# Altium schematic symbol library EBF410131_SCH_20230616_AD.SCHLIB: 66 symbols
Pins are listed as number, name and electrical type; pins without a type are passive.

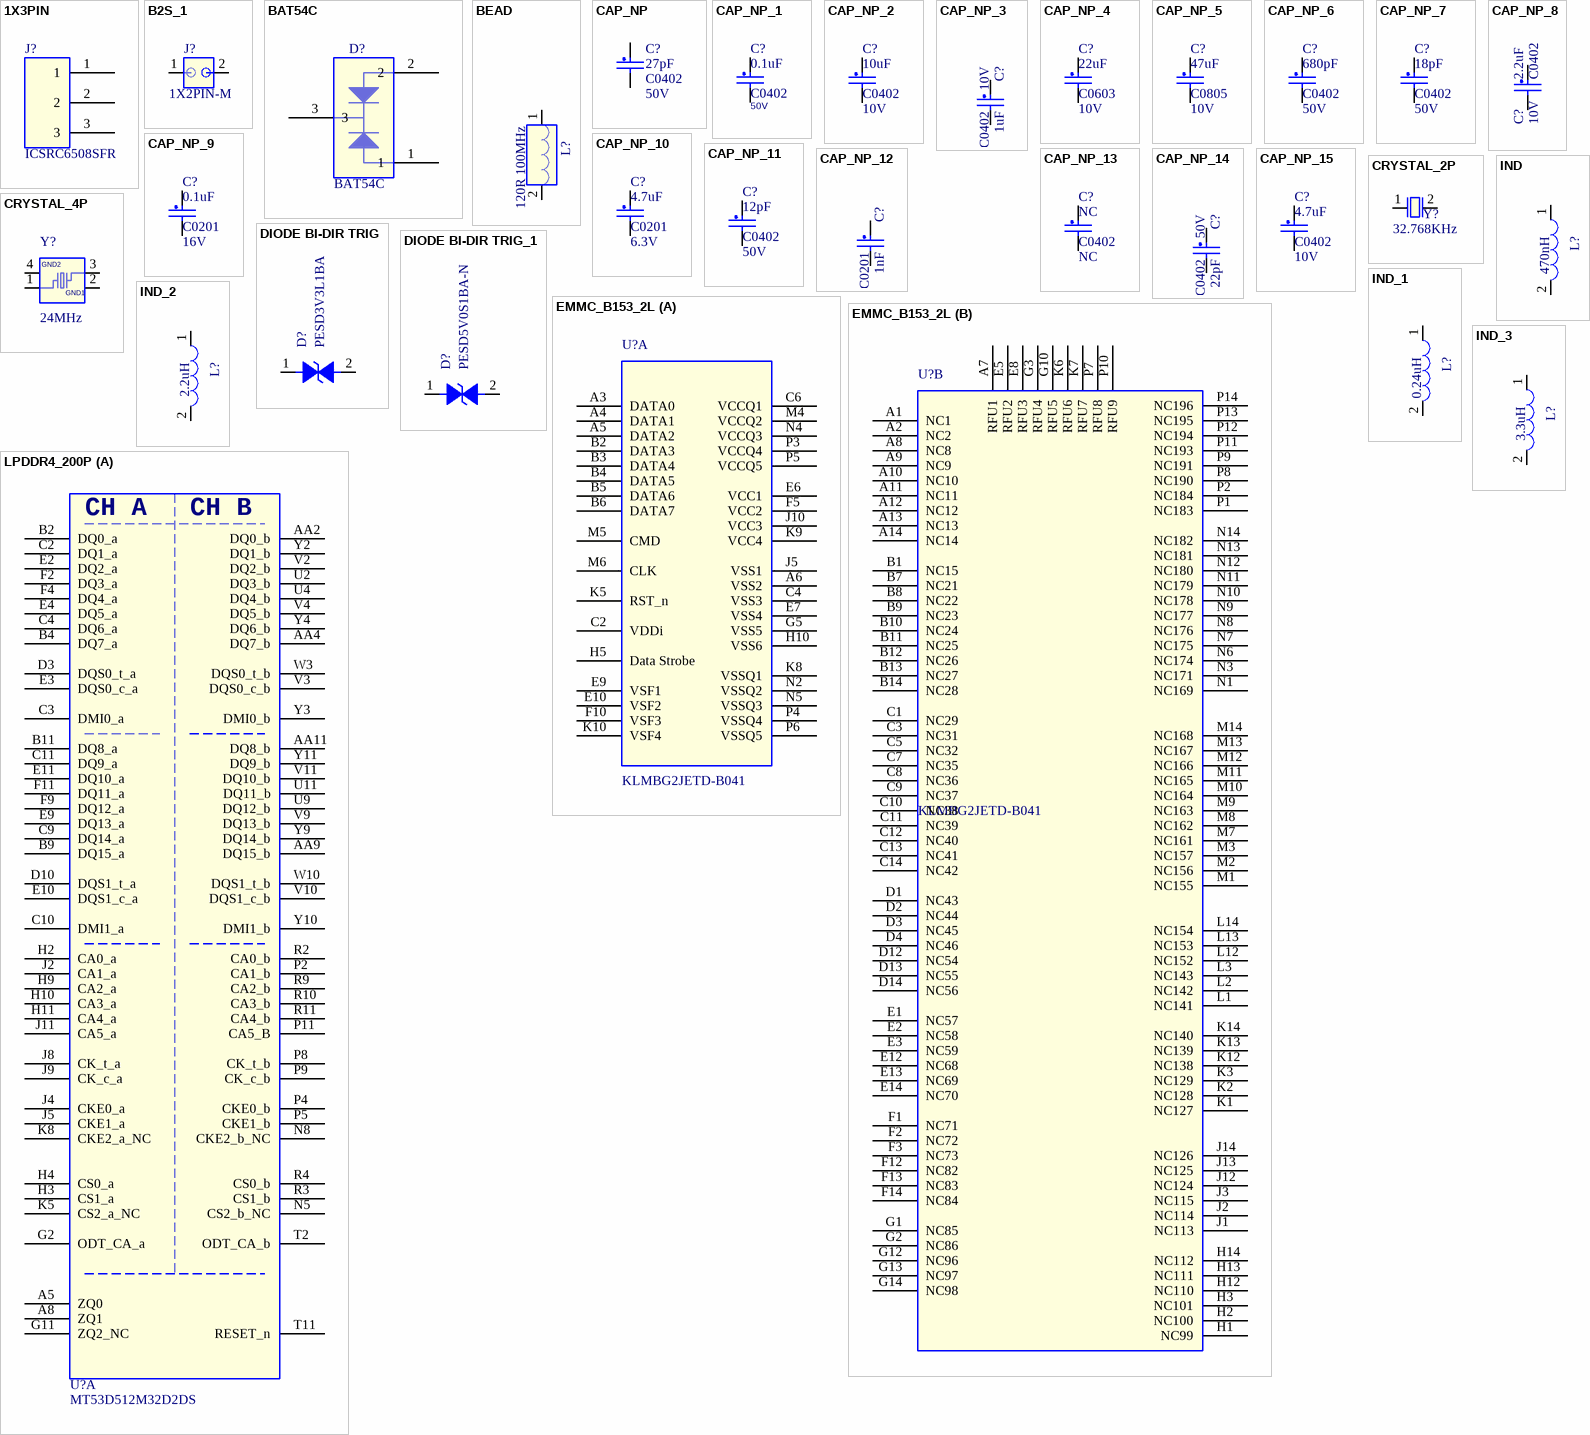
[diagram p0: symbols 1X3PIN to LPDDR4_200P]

## 1X3PIN
designator J?, comment ICSRC6508SFR
生命周期: 量产; 价格: 0.1; 规格书: ICT_ICSRC6508SFR.pdf; 类别: 屏蔽夹; 品牌: ICT; 条码: EBFCIS230316171123; 规格: ICSRC6508SFR 6.5x0.8x1.2(mm)
footprint ICSRC6508SFR
pins: 1, 2, 3

## B2S_1
designator J?, comment 1X2PIN-M
PCB Footprint: HDR-1RX2-1R50-TM-VR; 规格书: 州日_单排针_直插_2P54.pdf; 规格: 排针 总PIN数2 间距2.54mm 黑色直插; 条码: EBF29020033; 类别: 直插单排排针; 生命周期: 量产
footprint HDR-1RX2-1R50-TM-VR
pins: 1, 2

## BAT54C
designator D?
PCB Footprint: SOT23; 规格: 肖特基二极管 直流反向耐压30V 平均整流电流200mA 正向压降1V@100mA SOT-23; 条码: EBF29140014; 品牌: 萨科微; 类别: 贴片肖特基二极管; 规格书: BAT54C.pdf; 价格: 0.068489; 生命周期: 量产; 丝印: KL3
footprint SOT23
pins: 1, 2, 3

## BEAD
designator L?, comment 120R 100MHz
CLASS: DISCRETE; 规格: 磁珠120Ω @100MHz 额定电流1A 直流电阻120mΩ; 规格编号: PZ1005U121-1R0TF; 条码: EBF29050044; 品牌: 顺络; 类别: 贴片磁珠0402; 规格书: 顺络-磁珠120Ω±25%100MHZ.pdf; 价格: 0.020259; 生命周期: 量产; PCB Footprint: L0402
footprint L0402
pins: 1, 2

## CAP_NP
designator C?, comment 27pF  PCB Footprint: C0402  Voltage: 50V
CLASS: DISCRETE; 规格: 贴片电容27pF 5% 50V C0G 0402; 规格编号: 0402CG270J500NT; 条码: EBF29060296; 品牌: 风华; 类别: 贴片电容0402; 规格书: 风华电容.pdf; 价格: 0.003278; 生命周期: 量产
footprint C0402
pins: 1, 2

## CAP_NP_1
designator C?, comment 0.1uF  PCB Footprint: C0402  Voltage: 50V
CLASS: DISCRETE; 生命周期: 量产; 价格: 0.029826; 规格书: 风华电容.pdf; 类别: 贴片电容0402; 品牌: 风华; 条码: EBF29060118; 规格编号: 0402X104K500NT; 规格: 贴片电容0.1uF 10% 50V X5R 0402
footprint C0402
pins: 1, 2

## CAP_NP_2
designator C?, comment 10uF  PCB Footprint: C0402  Voltage: 10V
CLASS: DISCRETE; 生命周期: 量产; 价格: 0.518415; 规格书: 三星电容.pdf; 类别: 贴片电容0402; 品牌: 三星; 条码: EBF29060247; 规格编号: CL05A106MP8NUB8; 规格: 贴片电容10uF 20% 10V X5R 0402
footprint C0402
pins: 1, 2

## CAP_NP_3
designator C?, comment 1uF  PCB Footprint: C0402  Voltage: 10V
CLASS: DISCRETE; 规格: 贴片电容1uF 10% 10V X5R 0402; 规格编号: 0402X105K100NT; 条码: EBF29060121; 品牌: 风华; 类别: 贴片电容0402; 规格书: 风华电容.pdf; 价格: 0.01191; 生命周期: 量产
footprint C0402
pins: 1, 2

## CAP_NP_4
designator C?, comment 22uF  PCB Footprint: C0603  Voltage: 10V
CLASS: DISCRETE; 规格: 贴片电容22uF 20% 10V X5R 0603; 规格编号: CL10A226MP8NUNE; 条码: EBF29060163; 品牌: 三星; 类别: 贴片电容0603; 规格书: 三星电容.pdf; 价格: 0.078818; 生命周期: 量产
footprint C0603
pins: 1, 2

## CAP_NP_5
designator C?, comment 47uF  PCB Footprint: C0805  Voltage: 10V
CLASS: DISCRETE; 生命周期: 量产; 价格: 0.368494; 规格书: 风华电容.pdf; 类别: 贴片电容0805; 品牌: 风华; 条码: EBF29060212; 规格编号: 0805X476M100NT; 规格: 贴片电容47uF 20% 10V X5R 0805
footprint C0805
pins: 1, 2

## CAP_NP_6
designator C?, comment 680pF  PCB Footprint: C0402  Voltage: 50V
CLASS: DISCRETE; 规格: 贴片电容680pF 10% 50V X7R 0402; 规格编号: 0402B681K500NT; 条码: EBF29060295; 品牌: 风华; 类别: 贴片电容0402; 规格书: 风华电容.pdf; 价格: 0.003453; 生命周期: 量产
footprint C0402
pins: 1, 2

## CAP_NP_7
designator C?, comment 18pF  PCB Footprint: C0402  Voltage: 50V
CLASS: DISCRETE; 生命周期: 量产; 价格: 0.00515; 规格书: 风华电容.pdf; 类别: 贴片电容0402; 品牌: 风华; 条码: EBF29060235; 规格编号: 0402CG180J500NT; 规格: 贴片电容18pF 5% 50V C0G 0402
footprint C0402
pins: 1, 2

## CAP_NP_8
designator C?, comment 2.2uF  PCB Footprint: C0402  Voltage: 10V
CLASS: DISCRETE; 生命周期: 量产; 价格: 0.015858; 规格书: 三星电容.pdf; 类别: 贴片电容0402; 品牌: 三星; 条码: EBF29060265; 规格编号: CL05A225KP5NSNC; 规格: 贴片电容2.2uF 10% 10V X5R 0402
footprint C0402
pins: 1, 2

## CAP_NP_9
designator C?, comment 0.1uF  PCB Footprint: C0201  Voltage: 16V
CLASS: DISCRETE; 生命周期: 量产; 规格书: 三星电容.pdf; 类别: 贴片电容0201; 品牌: 三星; 条码: EBF29060189; 规格编号: CL03A104KO3NNNC; 规格: 贴片电容0.1uF 10% 16V X5R 0201; 价格: 0.006
footprint C0201
pins: 1, 2

## CAP_NP_10
designator C?, comment 4.7uF  PCB Footprint: C0201  Voltage: 6.3V
CLASS: DISCRETE; 生命周期: 量产; 价格: 0.399715; 规格书: 村田贴片电容.pdf; 类别: 贴片电容0201; 品牌: 村田; 条码: EBF29060234; 规格编号: GRM035R60J475ME15D; 规格: 贴片电容4.7uF 20% 6.3V X5R 0201
footprint C0201
pins: 1, 2

## CAP_NP_11
designator C?, comment 12pF  PCB Footprint: C0402  Voltage: 50V
CLASS: DISCRETE; 规格: 贴片电容12pF 5% 50V C0G 0402; 规格编号: 0402CG120J500NT; 条码: EBF29060297; 品牌: 风华; 类别: 贴片电容0402; 规格书: 风华电容.pdf; 价格: 0.003248; 生命周期: 量产
footprint C0402
pins: 1, 2

## CAP_NP_12
designator C?, comment 1nF  PCB Footprint: C0201
CLASS: DISCRETE; 生命周期: 量产; 价格: 0.00414; 规格书: 微容0201系列贴片电容.pdf; 类别: 贴片电容0201; 品牌: 微容; 条码: EBF29060303; 规格编号: V102K0201X7R500NAT; 规格: 贴片电容1nF 10% 50V X7R 0201
footprint C0201
pins: 1, 2

## CAP_NP_13
designator C?, comment NC  PCB Footprint: C0402
CLASS: DISCRETE; 类别: 贴片电容0402; 条码: EBF29060149; 规格: 贴片电容NC 预留
footprint C0402
pins: 1, 2

## CAP_NP_14
designator C?, comment 22pF  PCB Footprint: C0402  Voltage: 50V
CLASS: DISCRETE; 规格: 贴片电容22pF 5% 50V C0G 0402; 规格编号: 0402CG220J500NT; 条码: EBF29060220; 品牌: 三星; 类别: 贴片电容0402; 规格书: 三星电容.pdf; 价格: 0.004645; 生命周期: 量产
footprint C0402
pins: 1, 2

## CAP_NP_15
designator C?, comment 4.7uF  PCB Footprint: C0402  Voltage: 10V
CLASS: DISCRETE; 规格: 贴片电容4.7uF 10% 10V X5R 0402; 规格编号: CC0402KRX5R6BB475; 条码: EBF29060248; 品牌: 国巨; 类别: 贴片电容0402; 规格书: 国巨-贴片电容.pdf; 价格: 0.059058; 生命周期: 量产
footprint C0402
pins: 1, 2

## CRYSTAL_2P
designator Y?, comment 32.768KHz
规格: 无源晶振32.768KHz 70KΩ 9pF 3215; 规格编号: Q13FC1350000300; 条码: EBF29100004; 品牌: 爱普生; 类别: 贴片晶振 3215; 规格书: 爱普生-32.768KHz.pdf; 价格: 2.57; 生命周期: 量产; PCB Footprint: 3215
footprint 3215
pins: 1, 2

## CRYSTAL_4P
designator Y?, comment 24MHz
CLASS: IC; 规格: 无源晶振24MHZ 40Ω 12pF 3225; 规格编号: SX32Y024000BC1T; 条码: EBF29100003; 品牌: 泰晶; 类别: 贴片晶振 3225; PCB Footprint: 3225; 规格书: 泰晶-24MHz无源晶振.pdf; 价格: 0.436916; 生命周期: 量产
footprint 3225
pins: 1, 2 GND1 (power), 3, 4 GND2 (power)

## DIODE BI-DIR TRIG
designator D?, comment PESD3V3L1BA
PCB Footprint: sod323_t; 丝印: AB; 生命周期: 量产; 价格: 0.31497; 规格书: 安世-PESD3V3L1BA-115.pdf; 类别: 贴片ESD; 品牌: 安世; 条码: EBF29140003; 规格编号: PESD3V3L1BA 115; 规格: 防静电保护ESD二极管 箝位电压26V 击穿电压5.8V 反向关断电压3.3V
footprint D0603/SMD
footprint sod323_t
pins: 1, 2

## DIODE BI-DIR TRIG_1
designator D?, comment PESD5V0S1BA-N
PCB Footprint: SOD323; 规格: 防静电保护ESD二极管 箝位电压21V 击穿电压6V 反向关断电压5V; 条码: EBF29140021; 品牌: 伯恩半导体; 类别: 贴片ESD; 规格书: 伯恩半导体-PESD5V0S1BA-N.pdf; 价格: 0.196644; 生命周期: 量产
footprint D0603/SMD
footprint SOD323
pins: 1, 2

## EMMC_B153_2L
designator U?, comment KLMBG2JETD-B041
规格: eMMC 容量：32G 工作电压 Interface power : VDD (1.70V ~ 1.95V or 2.7V ~ 3.6V) Memory power : VDDF (2.7V ~ 3.6V); 条码: EBF2950033; 品牌: 三星; 类别: 存储器-eMMC; 规格书: KLMBG2JETD-B041.pdf; 生命周期: 量产
footprint FBGA153_0P5_11P5X13
part A pins: A3 DATA0, A4 DATA1, A5 DATA2, A6 VSS2, B2 DATA3, B3 DATA4, B4 DATA5, B5 DATA6, B6 DATA7, C2 VDDi, C4 VSS3, C6 VCCQ1, E6 VCC1, E7 VSS4, E9 VSF1, E10 VSF2, F5 VCC2, F10 VSF3, G5 VSS5, H5 Data Strobe, H10 VSS6, J5 VSS1, J10 VCC3, K5 RST_n, K8 VSSQ1, K9 VCC4, K10 VSF4, M4 VCCQ2, M5 CMD, M6 CLK, N2 VSSQ2, N4 VCCQ3, N5 VSSQ3, P3 VCCQ4, P4 VSSQ4, P5 VCCQ5, P6 VSSQ5
part B pins: A1 NC1, A2 NC2, A7 RFU1, A8 NC8, A9 NC9, A10 NC10, A11 NC11, A12 NC12, A13 NC13, A14 NC14, B1 NC15, B7 NC21, B8 NC22, B9 NC23, B10 NC24, B11 NC25, B12 NC26, B13 NC27, B14 NC28, C1 NC29, C3 NC31, C5 NC32, C7 NC35, C8 NC36, C9 NC37, C10 NC38, C11 NC39, C12 NC40, C13 NC41, C14 NC42, D1 NC43, D2 NC44, D3 NC45, D4 NC46, D12 NC54, D13 NC55, D14 NC56, E1 NC57, E2 NC58, E3 NC59, E5 RFU2, E8 RFU3, E12 NC68, E13 NC69, E14 NC70, F1 NC71, F2 NC72, F3 NC73, F12 NC82, F13 NC83, F14 NC84, G1 NC85, G2 NC86, G3 RFU4, G10 RFU5, G12 NC96, G13 NC97, G14 NC98, H1 NC99, H2 NC100, H3 NC101, H12 NC110, H13 NC111, H14 NC112, J1 NC113, J2 NC114, J3 NC115, J12 NC124, J13 NC125, J14 NC126, K1 NC127, K2 NC128, K3 NC129, K6 RFU6, K7 RFU7, K12 NC138, K13 NC139, K14 NC140, L1 NC141, L2 NC142, L3 NC143, L12 NC152, L13 NC153, L14 NC154, M1 NC155, M2 NC156, M3 NC157, M7 NC161, M8 NC162, M9 NC163, M10 NC164, M11 NC165, M12 NC166, M13 NC167, M14 NC168, N1 NC169, N3 NC171, N6 NC174, N7 NC175, N8 NC176, N9 NC177, N10 NC178, N11 NC179, N12 NC180, N13 NC181, N14 NC182, P1 NC183, P2 NC184, P7 RFU8, P8 NC190, P9 NC191, P10 RFU9, P11 NC193, P12 NC194, P13 NC195, P14 NC196

## IND
designator L?, comment 470nH
CLASS: DISCRETE; 生命周期: 量产; 价格: 0.175312; 规格书: 佳邦_WIP252012P-R47ML.pdf; 类别: 贴片电感2520; 品牌: 佳邦; 条码: EBF29050046; 规格编号: WIP252012P-R47ML; 规格: 功率电感470nH ±20% 4.18A 直流电阻22mΩ; PCB Footprint: L2520
footprint L2520
pins: 1, 2

## IND_1
designator L?, comment 0.24uH
CLASS: DISCRETE; 规格: 功率电感0.24uH ±20% 4.05A 直流电阻19mΩ; 规格编号: WPN252012HR24MT; 条码: EBF29050066; 品牌: 顺络; 类别: 贴片电感2520; 规格书: 顺络WPN系列功率电感.pdf; 生命周期: 量产; PCB Footprint: L2520
footprint L2520
pins: 1, 2

## IND_2
designator L?, comment 2.2uH
CLASS: DISCRETE; 规格: 功率电感2.2uH 2.2uH ±20% 2.06A 85mΩ; 规格编号: WIP252012P-2R2ML; 条码: EBFCIS220927171910; 品牌: 佳邦; 类别: 贴片电感2520; 规格书: 佳邦_ WIP252012P-2R2ML.pdf; 价格: 0.129914; 生命周期: 量产; PCB Footprint: L2520
footprint L2520
pins: 1, 2

## IND_3
designator L?, comment 3.3uH
CLASS: DISCRETE; 生命周期: 量产; 规格书: 台庆-功率电感.pdf; 类别: 贴片电感0402; 品牌: 台庆; 条码: EBF29050040; 规格: 贴片电感3.3uH ±20% 3A 直流电阻69mΩ; 规格编号: TMPC0402HP-3R3MG-Z02; 价格: 1.5992; PCB Footprint: l4520
footprint l4520
pins: 1, 2

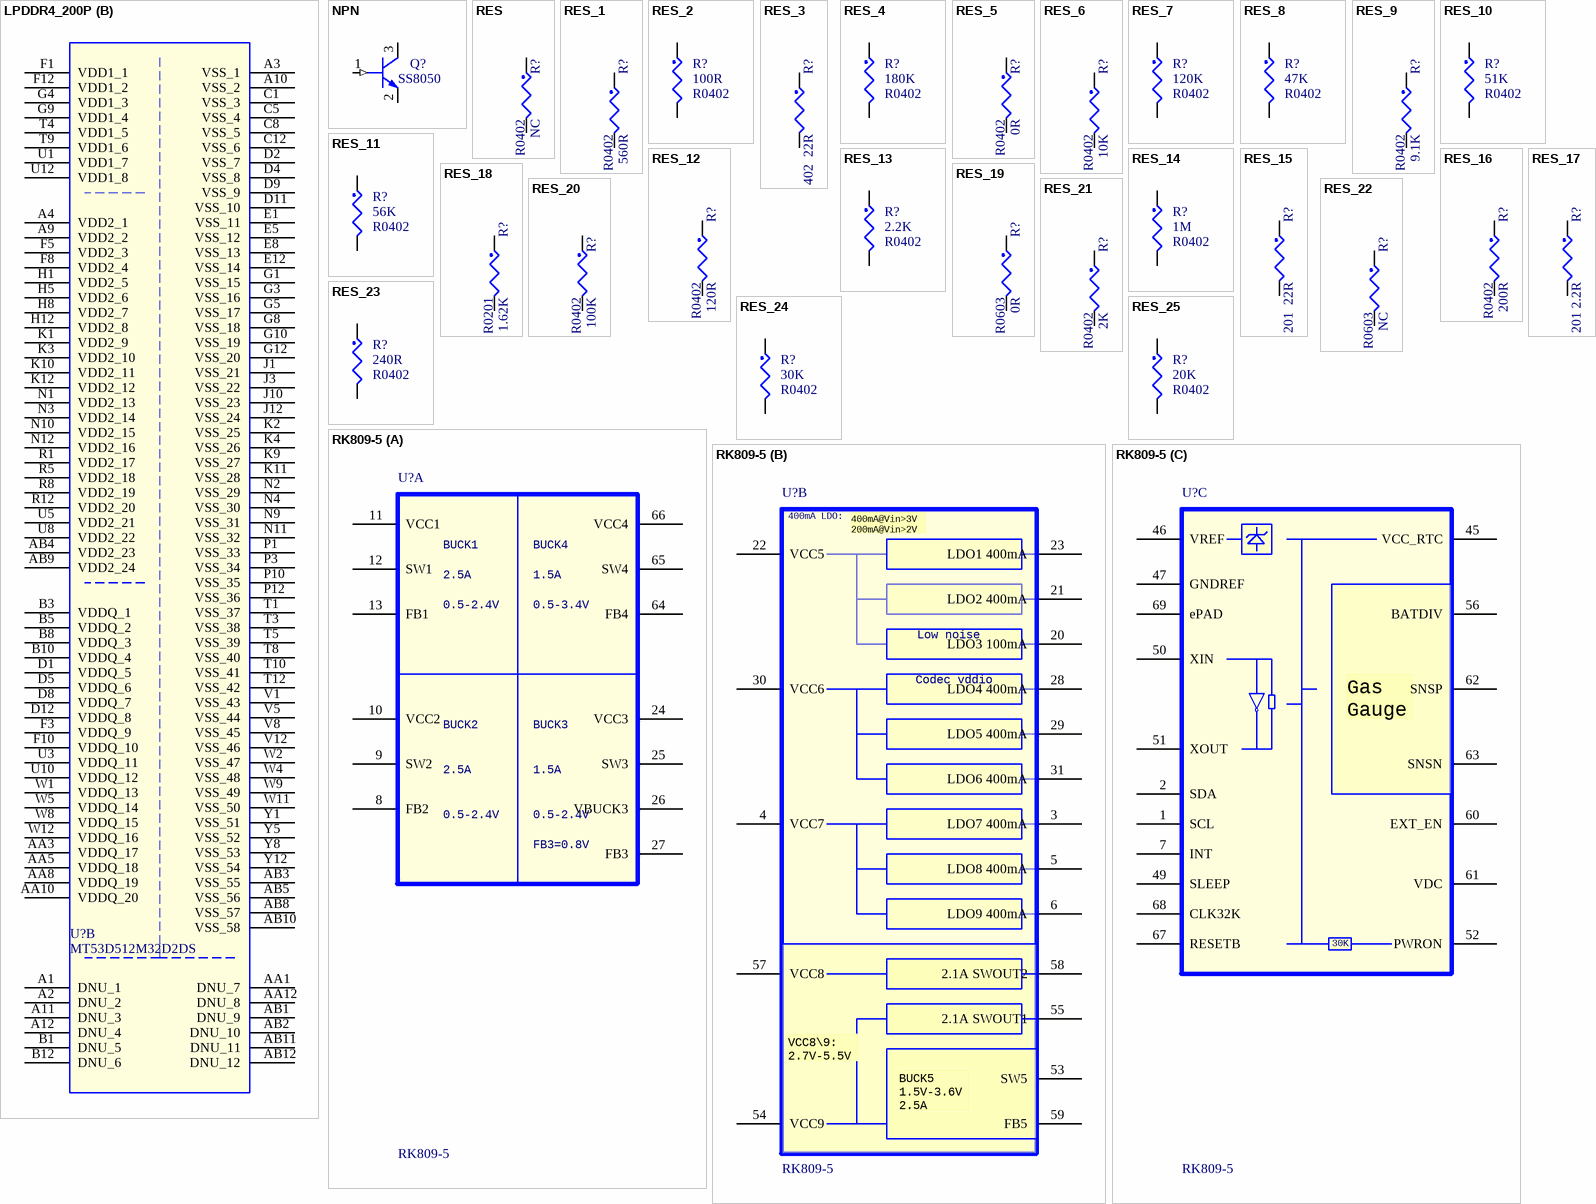
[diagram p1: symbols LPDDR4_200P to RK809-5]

## LPDDR4_200P
designator U?, comment MT53D512M32D2DS
PCB Footprint: bga200_15r00x10r00x0r90; 规格: DDR4 SDRAM 大小：16Gb(512Mx32); 规格编号: MT53D512M32D2DS-053WT:D; 条码: EBF2950034; 品牌: 镁光; 类别: 存储器-DRAM; 规格书: Micron-Tech-MT53D512M32D2DS-053-WT-D.pdf; 生命周期: 量产
footprint bga200_15r00x10r00x0r90
part A pins: A5 ZQ0, A8 ZQ1, AA2 DQ0_b, AA4 DQ7_b, AA9 DQ15_b, AA11 DQ8_b, B2 DQ0_a, B4 DQ7_a, B9 DQ15_a, B11 DQ8_a, C2 DQ1_a, C3 DMI0_a, C4 DQ6_a, C9 DQ14_a, C10 DMI1_a, C11 DQ9_a, D3 DQS0_t_a, D10 DQS1_t_a, E2 DQ2_a, E3 DQS0_c_a, E4 DQ5_a, E9 DQ13_a, E10 DQS1_c_a, E11 DQ10_a, F2 DQ3_a, F4 DQ4_a, F9 DQ12_a, F11 DQ11_a, G2 ODT_CA_a, G11 ZQ2_NC, H2 CA0_a, H3 CS1_a, H4 CS0_a, H9 CA2_a, H10 CA3_a, H11 CA4_a, J2 CA1_a, J4 CKE0_a, J5 CKE1_a, J8 CK_t_a, J9 CK_c_a, J11 CA5_a, K5 CS2_a_NC, K8 CKE2_a_NC, N5 CS2_b_NC, N8 CKE2_b_NC, P2 CA1_b, P4 CKE0_b, P5 CKE1_b, P8 CK_t_b, P9 CK_c_b, P11 CA5_B, R2 CA0_b, R3 CS1_b, R4 CS0_b, R9 CA2_b, R10 CA3_b, R11 CA4_b, T2 ODT_CA_b, T11 RESET_n, U2 DQ3_b, U4 DQ4_b, U9 DQ12_b, U11 DQ11_b, V2 DQ2_b, V3 DQS0_c_b, V4 DQ5_b, V9 DQ13_b, V10 DQS1_c_b, V11 DQ10_b, W3 DQS0_t_b, W10 DQS1_t_b, Y2 DQ1_b, Y3 DMI0_b, Y4 DQ6_b, Y9 DQ14_b, Y10 DMI1_b, Y11 DQ9_b
part B pins: A1 DNU_1, A2 DNU_2, A3 VSS_1 (power), A4 VDD2_1 (power), A9 VDD2_2 (power), A10 VSS_2 (power), A11 DNU_3, A12 DNU_4, AA1 DNU_7, AA3 VDDQ_17 (power), AA5 VDDQ_18 (power), AA8 VDDQ_19 (power), AA10 VDDQ_20 (power), AA12 DNU_8, AB1 DNU_9, AB2 DNU_10, AB3 VSS_55 (power), AB4 VDD2_23 (power), AB5 VSS_56 (power), AB8 VSS_57 (power), AB9 VDD2_24 (power), AB10 VSS_58 (power), AB11 DNU_11, AB12 DNU_12, B1 DNU_5, B3 VDDQ_1 (power), B5 VDDQ_2 (power), B8 VDDQ_3 (power), B10 VDDQ_4 (power), B12 DNU_6, C1 VSS_3 (power), C5 VSS_4 (power), C8 VSS_5 (power), C12 VSS_6 (power), D1 VDDQ_5 (power), D2 VSS_7 (power), D4 VSS_8 (power), D5 VDDQ_6 (power), D8 VDDQ_7 (power), D9 VSS_9 (power), D11 VSS_10 (power), D12 VDDQ_8 (power), E1 VSS_11 (power), E5 VSS_12 (power), E8 VSS_13 (power), E12 VSS_14 (power), F1 VDD1_1 (power), F3 VDDQ_9 (power), F5 VDD2_3 (power), F8 VDD2_4 (power), F10 VDDQ_10 (power), F12 VDD1_2 (power), G1 VSS_15 (power), G3 VSS_16 (power), G4 VDD1_3 (power), G5 VSS_17 (power), G8 VSS_18 (power), G9 VDD1_4 (power), G10 VSS_19 (power), G12 VSS_20 (power), H1 VDD2_5 (power), H5 VDD2_6 (power), H8 VDD2_7 (power), H12 VDD2_8 (power), J1 VSS_21 (power), J3 VSS_22 (power), J10 VSS_23 (power), J12 VSS_24 (power), K1 VDD2_9 (power), K2 VSS_25 (power), K3 VDD2_10 (power), K4 VSS_26 (power), K9 VSS_27 (power), K10 VDD2_11 (power), K11 VSS_28 (power), K12 VDD2_12 (power), N1 VDD2_13 (power), N2 VSS_29 (power), N3 VDD2_14 (power), N4 VSS_30 (power), N9 VSS_31 (power), N10 VDD2_15 (power), N11 VSS_32 (power), N12 VDD2_16 (power), P1 VSS_33 (power), P3 VSS_34 (power), P10 VSS_35 (power), P12 VSS_36 (power), R1 VDD2_17 (power), R5 VDD2_18 (power), R8 VDD2_19 (power), R12 VDD2_20 (power), T1 VSS_37 (power), T3 VSS_38 (power), T4 VDD1_5 (power), T5 VSS_39 (power), T8 VSS_40 (power), T9 VDD1_6 (power), T10 VSS_41 (power), T12 VSS_42 (power), U1 VDD1_7 (power), U3 VDDQ_11 (power), U5 VDD2_21 (power), U8 VDD2_22 (power), U10 VDDQ_12 (power), U12 VDD1_8 (power), V1 VSS_43 (power), V5 VSS_44 (power), V8 VSS_45 (power), V12 VSS_46 (power), W1 VDDQ_13 (power), W2 VSS_47 (power), W4 VSS_48 (power), W5 VDDQ_14 (power), W8 VDDQ_15 (power), W9 VSS_49 (power), W11 VSS_50 (power), W12 VDDQ_16 (power), Y1 VSS_51 (power), Y5 VSS_52 (power), Y8 VSS_53 (power), Y12 VSS_54 (power)

## NPN
designator Q?, comment SS8050
CLASS: IC; 规格: 贴片三极管SS8050 集电极电流1.5A 额定功率300mW NPN; 条码: EBF29090001; 品牌: 江苏长电; 类别: 贴片三极管SOT-23; 规格书: 江苏长电-SS8050Y1.pdf; 价格: 0.086744; 生命周期: 量产; 丝印: Y1; PCB Footprint: SOT23
footprint SOT23
pins: 1 BASE (in), 2 EMITTER, 3 COLLECTOR

## RES
designator R?, comment NC  PCB Footprint: R0402
CLASS: DISCRETE; 类别: 贴片电阻0402; 条码: EBF29070087; 规格: 贴片电阻NC 预留
footprint R0402
pins: 1, 2

## RES_1
designator R?, comment 560R  PCB Footprint: R0402
CLASS: DISCRETE; 生命周期: 量产; 价格: 0.002258; 规格书: 厚声-无铅厚膜电阻.pdf; 类别: 贴片电阻0402; 品牌: 厚声; 条码: EBF29070272; 规格编号: 0402WGF5600TCE; 规格: 贴片电阻560R 1% 1/16W 0402
footprint R0402
pins: 1, 2

## RES_2
designator R?, comment 100R  PCB Footprint: R0402
CLASS: DISCRETE; 生命周期: 量产; 规格书: 合科泰-RI系列电阻.pdf; 类别: 贴片电阻0402; 品牌: 合科泰; 条码: EBF29070053; 规格编号: RI0402L1000FT; 规格: 贴片电阻100R 1% 1/16W 0402
footprint R0402
pins: 1, 2

## RES_3
designator R?, comment 22R  PCB Footprint: R0402
CLASS: DISCRETE; 生命周期: 量产; 规格书: 合科泰-RI系列电阻.pdf; 类别: 贴片电阻0402; 品牌: 合科泰; 条码: EBF29070181; 规格编号: RI0402L22R0FT; 规格: 贴片电阻22R 1% 1/16W 0402
footprint R0402
pins: 1, 2

## RES_4
designator R?, comment 180K  PCB Footprint: R0402
CLASS: DISCRETE; 规格: 贴片电阻180K 1% 1/16W 0402; 规格编号: CQ02WGF1803TCE; 条码: EBF29070288; 品牌: 厚声; 类别: 贴片电阻0402; 规格书: 厚声-无铅厚膜电阻.pdf; 价格: 0.006152; 生命周期: 量产
footprint R0402
pins: 1, 2

## RES_5
designator R?, comment 0R  PCB Footprint: R0402
CLASS: DISCRETE; 规格: 贴片电阻0R 1% 1/16W 0402; 规格编号: RI0402L000FT; 条码: EBF29070049; 品牌: 合科泰; 类别: 贴片电阻0402; 规格书: 合科泰-RI系列电阻.pdf; 生命周期: 量产
footprint R0402
pins: 1, 2

## RES_6
designator R?, comment 10K  PCB Footprint: R0402
CLASS: DISCRETE; 规格: 贴片电阻10K 1% 1/16W 0402; 规格编号: 0402WGF1002TCE; 条码: EBF29070046; 品牌: 厚声; 类别: 贴片电阻0402; 规格书: 厚声-无铅厚膜电阻.pdf; 价格: 0.002773; 生命周期: 量产
footprint R0402
pins: 1, 2

## RES_7
designator R?, comment 120K  PCB Footprint: R0402
CLASS: DISCRETE; 规格: 贴片电阻120K 1% 1/16W 0402; 规格编号: 0402WGF1203TCE; 条码: EBF29070273; 品牌: 厚声; 类别: 贴片电阻0402; 规格书: 厚声-无铅厚膜电阻.pdf; 价格: 0.00237; 生命周期: 量产
footprint R0402
pins: 1, 2

## RES_8
designator R?, comment 47K  PCB Footprint: R0402
CLASS: DISCRETE; 规格: 贴片电阻47K 1% 1/16W 0402; 规格编号: 0402WGF4702TCE; 条码: EBF29070247; 品牌: 厚声; 类别: 贴片电阻0402; 规格书: 厚声-无铅厚膜电阻.pdf; 生命周期: 量产
footprint R0402
pins: 1, 2

## RES_9
designator R?, comment 9.1K  PCB Footprint: R0402
CLASS: DISCRETE; 规格: 贴片电阻9.1K 1% 1/16W 0402; 规格编号: 0402WGF9101TCE; 条码: EBF29070277; 品牌: 厚声; 类别: 贴片电阻0402; 规格书: 厚声-无铅厚膜电阻.pdf; 价格: 0.002433; 生命周期: 量产
footprint R0402
pins: 1, 2

## RES_10
designator R?, comment 51K  PCB Footprint: R0402
CLASS: DISCRETE; 生命周期: 量产; 价格: 0.002838; 规格书: 厚声-无铅厚膜电阻.pdf; 类别: 贴片电阻0402; 品牌: 厚声; 条码: EBF29070235; 规格编号: 0402WGF5102TCE; 规格: 贴片电阻51K 1% 1/16W 0402
footprint R0402
pins: 1, 2

## RES_11
designator R?, comment 56K  PCB Footprint: R0402
CLASS: DISCRETE; 生命周期: 量产; 价格: 0.002324; 规格书: 厚声-无铅厚膜电阻.pdf; 类别: 贴片电阻0402; 品牌: 厚声; 条码: EBF29070274; 规格编号: 0402WGF5602TCE; 规格: 贴片电阻56K 1% 1/16W 0402
footprint R0402
pins: 1, 2

## RES_12
designator R?, comment 120R  PCB Footprint: R0402
CLASS: DISCRETE; 生命周期: 量产; 价格: 0.002198; 规格书: 厚声-无铅厚膜电阻.pdf; 类别: 贴片电阻0402; 品牌: 厚声; 条码: EBF29070275; 规格编号: 0402WGF1200TCE; 规格: 贴片电阻120R 1% 1/16W 0402
footprint R0402
pins: 1, 2

## RES_13
designator R?, comment 2.2K  PCB Footprint: R0402
CLASS: DISCRETE; 生命周期: 量产; 规格书: 合科泰-RI系列电阻.pdf; 类别: 贴片电阻0402; 品牌: 合科泰; 条码: EBF29070051; 规格编号: RI0402L2201FT; 规格: 贴片电阻2.2K 1% 1/16W 0402
footprint R0402
pins: 1, 2

## RES_14
designator R?, comment 1M  PCB Footprint: R0402
CLASS: DISCRETE; 规格: 贴片电阻1M 1% 1/16W 0402; 规格编号: RI0402L1004FT; 条码: EBF29070062; 品牌: 厚声; 类别: 贴片电阻0402; 规格书: 合科泰-RI系列电阻.pdf; 生命周期: 量产
footprint R0402
pins: 1, 2

## RES_15
designator R?, comment 22R  PCB Footprint: R0201
CLASS: DISCRETE; 生命周期: 量产; 价格: 0.00631; 规格书: 国巨贴片电阻.pdf; 类别: 贴片电阻0201; 品牌: 国巨; 条码: EBF29070004; 规格编号: RC0201FR-0722RL; 规格: 贴片电阻22R 1% 1/20W 0201
footprint R0201
pins: 1, 2

## RES_16
designator R?, comment 200R  PCB Footprint: R0402
CLASS: DISCRETE; 生命周期: 量产; 规格书: 合科泰-RI系列电阻.pdf; 类别: 贴片电阻0402; 品牌: 合科泰; 条码: EBF29070239; 规格编号: RI0603L2000FT; 规格: 贴片电阻200R 1% 1/16W 0402
footprint R0402
pins: 1, 2

## RES_17
designator R?, comment 2.2R  PCB Footprint: R0201
CLASS: DISCRETE; 生命周期: 量产; 价格: 0.007671; 规格书: 厚声-无铅厚膜电阻.pdf; 类别: 贴片电阻0201; 品牌: 厚声; 条码: EBF29070278; 规格编号: 0201WMF220KTEE; 规格: 贴片电阻2.2R 1% 1/20W 0201
footprint R0201
pins: 1, 2

## RES_18
designator R?, comment 1.62K  PCB Footprint: R0201
CLASS: DISCRETE; 规格: 贴片电阻1.62K 1% 1/20W 0201; 规格编号: 0201WMF1621TEE; 条码: EBF29070279; 品牌: 厚声; 类别: 贴片电阻0201; 规格书: 厚声-无铅厚膜电阻.pdf; 价格: 0.003932; 生命周期: 量产
footprint R0201
pins: 1, 2

## RES_19
designator R?, comment 0R  PCB Footprint: R0603
CLASS: DISCRETE; 规格: 贴片电阻0R 1% 1/10W 0603; 规格编号: RI0603L0000FT; 条码: EBF29070063; 品牌: 合科泰; 类别: 贴片电阻0603; 规格书: 合科泰-RI系列电阻.pdf; 生命周期: 量产
footprint R0603
pins: 1, 2

## RES_20
designator R?, comment 100K  PCB Footprint: R0402
CLASS: DISCRETE; 生命周期: 量产; 规格书: 合科泰-RI系列电阻.pdf; 类别: 贴片电阻0402; 品牌: 合科泰; 条码: EBF29070054; 规格编号: RI0402L1003FT; 规格: 贴片电阻100K 1% 1/16W 0402
footprint R0402
pins: 1, 2

## RES_21
designator R?, comment 2K  PCB Footprint: R0402
CLASS: DISCRETE; 生命周期: 量产; 价格: 0.002298; 规格书: 厚声-无铅厚膜电阻.pdf; 类别: 贴片电阻0402; 品牌: 厚声; 条码: EBF29070188; 规格编号: 0402WGF2001TCE; 规格: 贴片电阻2K 1% 1/16W 0402
footprint R0402
pins: 1, 2

## RES_22
designator R?, comment NC  PCB Footprint: R0603
CLASS: DISCRETE; 类别: 贴片电阻0603; 条码: EBF29070088; 规格: 贴片电阻NC 预留
footprint R0603
pins: 1, 2

## RES_23
designator R?, comment 240R  PCB Footprint: R0402
CLASS: DISCRETE; 规格: 贴片电阻240R 1% 1/16W 0402; 规格编号: RI0402L2400FT; 条码: EBF29070183; 品牌: 合科泰; 类别: 贴片电阻0402; 规格书: 合科泰-RI系列电阻.pdf; 生命周期: 量产
footprint R0402
pins: 1, 2

## RES_24
designator R?, comment 30K  PCB Footprint: R0402
CLASS: DISCRETE; 规格: 贴片电阻30K 1% 1/16W 0402; 规格编号: RI0402L3002FT; 条码: EBF29070048; 品牌: 合科泰; 类别: 贴片电阻0402; 规格书: 合科泰-RI系列电阻.pdf; 生命周期: 量产
footprint R0402
pins: 1, 2

## RES_25
designator R?, comment 20K  PCB Footprint: R0402
CLASS: DISCRETE; 规格: 贴片电阻20K 1% 1/16W 0402; 规格编号: 0402WGF2002TCE; 条码: EBF29070223; 品牌: 厚声; 类别: 贴片电阻0402; 规格书: 厚声-无铅厚膜电阻.pdf; 价格: 0.002473; 生命周期: 量产
footprint R0402
pins: 1, 2

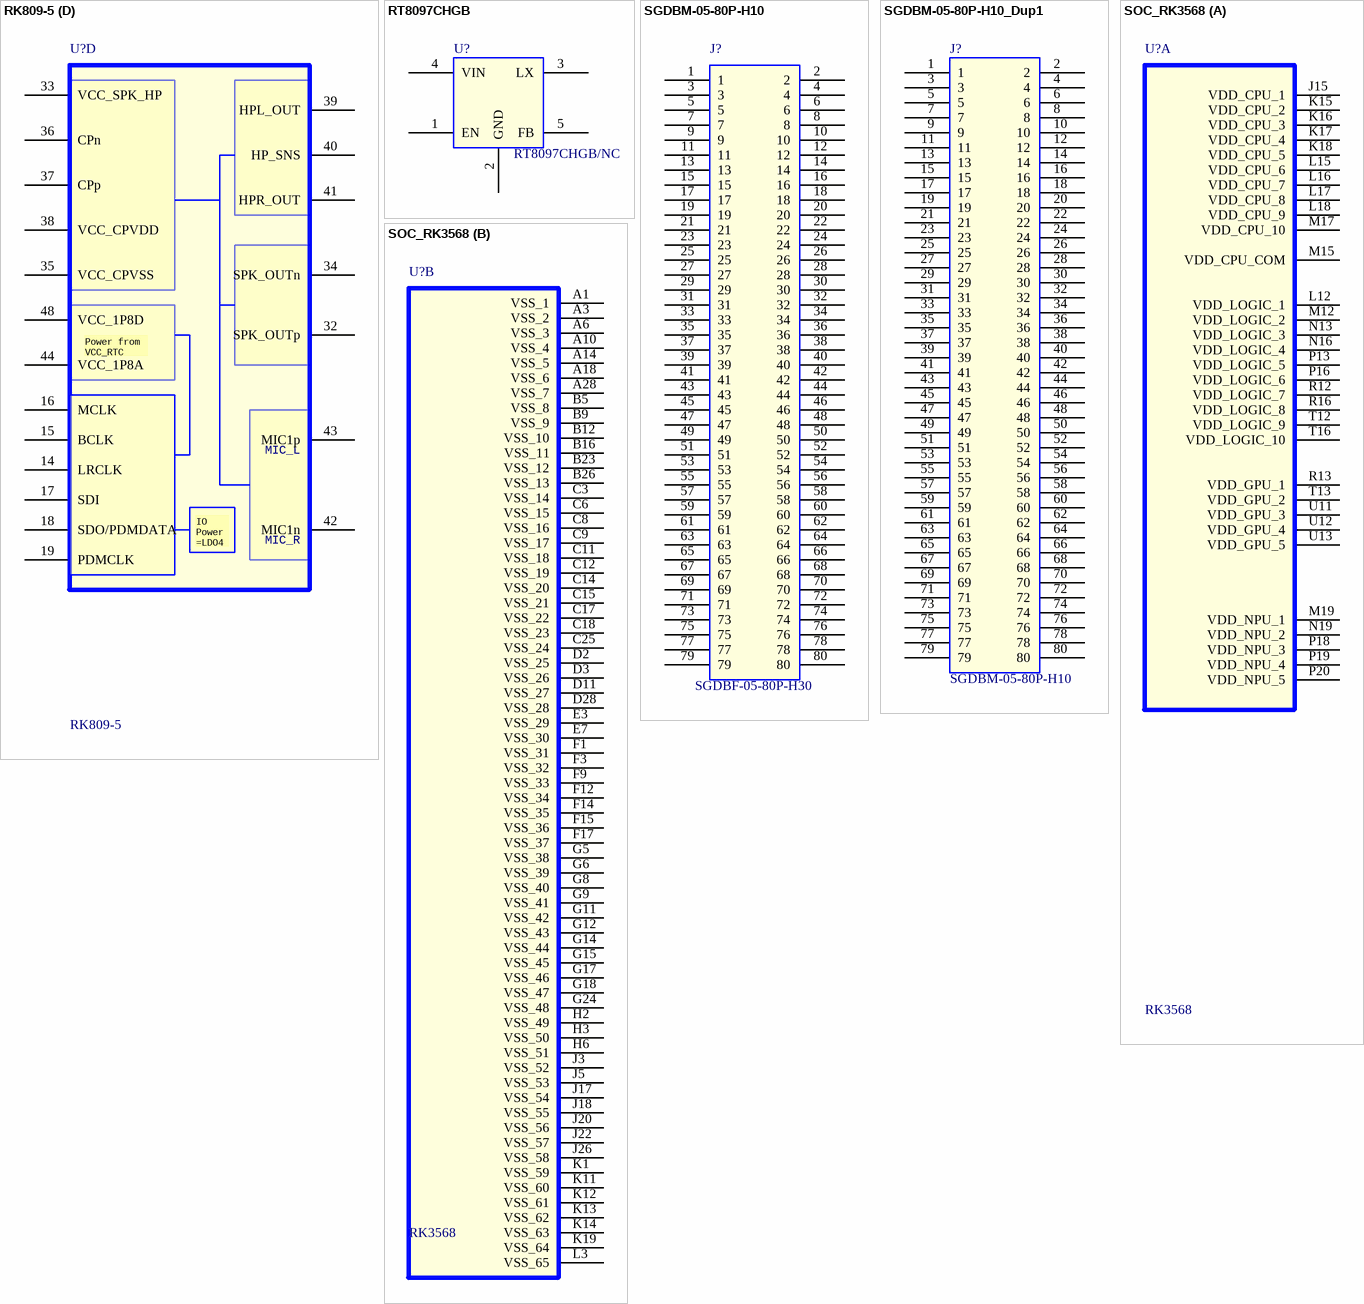
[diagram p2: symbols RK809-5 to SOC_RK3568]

## RK809-5
designator U?
生命周期: 量产; 规格书: RK809_V1.7.pdf; 类别: 电源管理-PMU; 品牌: 瑞芯微; 条码: EBF29110050; 规格: DC-DC电源芯片 可输出电流 1.5/2.5A 输入电压：2.7V~5.5V 最大输出电压：0.5-3.6V 5路输出; PCB Footprint: qfn68_7r00x7r00x0r80
footprint QFN68_7R00X7R00X0R80_T
footprint qfn68_7r00x7r00x0r80
part A pins: 8 FB2, 9 SW2, 10 VCC2, 11 VCC1, 12 SW1, 13 FB1, 24 VCC3, 25 SW3, 26 VBUCK3, 27 FB3, 64 FB4, 65 SW4, 66 VCC4
part B pins: 3 LDO7 400mA, 4 VCC7, 5 LDO8 400mA, 6 LDO9 400mA, 20 LDO3 100mA, 21 LDO2 400mA, 22 VCC5, 23 LDO1 400mA, 28 LDO4 400mA, 29 LDO5 400mA, 30 VCC6, 31 LDO6 400mA, 53 SW5, 54 VCC9, 55 2.1A SWOUT1, 57 VCC8, 58 2.1A SWOUT2, 59 FB5
part C pins: 1 SCL, 2 SDA, 7 INT, 45 VCC_RTC, 46 VREF, 47 GNDREF, 49 SLEEP, 50 XIN, 51 XOUT, 52 PWRON, 56 BATDIV, 60 EXT_EN, 61 VDC, 62 SNSP, 63 SNSN, 67 RESETB, 68 CLK32K, 69 ePAD
part D pins: 14 LRCLK, 15 BCLK, 16 MCLK, 17 SDI, 18 SDO/PDMDATA, 19 PDMCLK, 32 SPK_OUTp, 33 VCC_SPK_HP, 34 SPK_OUTn, 35 VCC_CPVSS, 36 CPn, 37 CPp, 38 VCC_CPVDD, 39 HPL_OUT, 40 HP_SNS, 41 HPR_OUT, 42 MIC1n, 43 MIC1p, 44 VCC_1P8A, 48 VCC_1P8D

## RT8097CHGB
designator U?, comment RT8097CHGB/NC
可替代料: EBF29110025; 生命周期: 量产; 价格: 1.3168; 规格书: RICHTEK(台湾立锜)_RT8097CHGB.pdf; 类别: 电源管理-DCDC; 品牌: 台湾立锜; 规格: 可调DCDC 输入电压2.7V~6V 输出电压0.6V~3.4V 最大输出电流：2A 自带内部同步整流 开关频率：1MHz; PCB Footprint: TSOT-23-5
footprint TSOT-23-5
pins: 1 EN, 2 GND (power), 3 LX (power), 4 VIN (power), 5 FB

## SGDBM-05-80P-H10
designator J?, comment SGDBF-05-80P-H30
规格: 0.5mm BTB母座2*40P 双槽 立贴式 合高4.0mm; 条码: EBFCIS221220165510; 品牌: 山谷道; 类别: BTB连接器; 规格书: 山谷道_双槽板对板公母立贴式0_5mm.pdf; 生命周期: 量产
footprint SGDBF-05-80P-H30
pins: 1, 2, 3, 4, 5, 6, 7, 8, 9, 10, 11, 12, 13, 14, 15, 16, 17, 18, 19, 20, 21, 22, 23, 24, 25, 26, 27, 28, 29, 30, 31, 32, 33, 34, 35, 36, 37, 38, 39, 40, 41, 42, 43, 44, 45, 46, 47, 48, 49, 50, 51, 52, 53, 54, 55, 56, 57, 58, 59, 60, 61, 62, 63, 64, 65, 66, 67, 68, 69, 70, 71, 72, 73, 74, 75, 76, 77, 78, 79, 80

## SGDBM-05-80P-H10_Dup1
designator J?, comment SGDBM-05-80P-H10
生命周期: 量产; 规格书: 山谷道_双槽板对板公母立贴式0_5mm.pdf; 类别: BTB连接器; 品牌: 山谷道; 条码: EBFCIS221220164941; 规格: 0.5mm BTB公座2*40P 双槽 立贴式 合高4.0mm
footprint SGDBM-05-80P-H10
pins: 1, 2, 3, 4, 5, 6, 7, 8, 9, 10, 11, 12, 13, 14, 15, 16, 17, 18, 19, 20, 21, 22, 23, 24, 25, 26, 27, 28, 29, 30, 31, 32, 33, 34, 35, 36, 37, 38, 39, 40, 41, 42, 43, 44, 45, 46, 47, 48, 49, 50, 51, 52, 53, 54, 55, 56, 57, 58, 59, 60, 61, 62, 63, 64, 65, 66, 67, 68, 69, 70, 71, 72, 73, 74, 75, 76, 77, 78, 79, 80

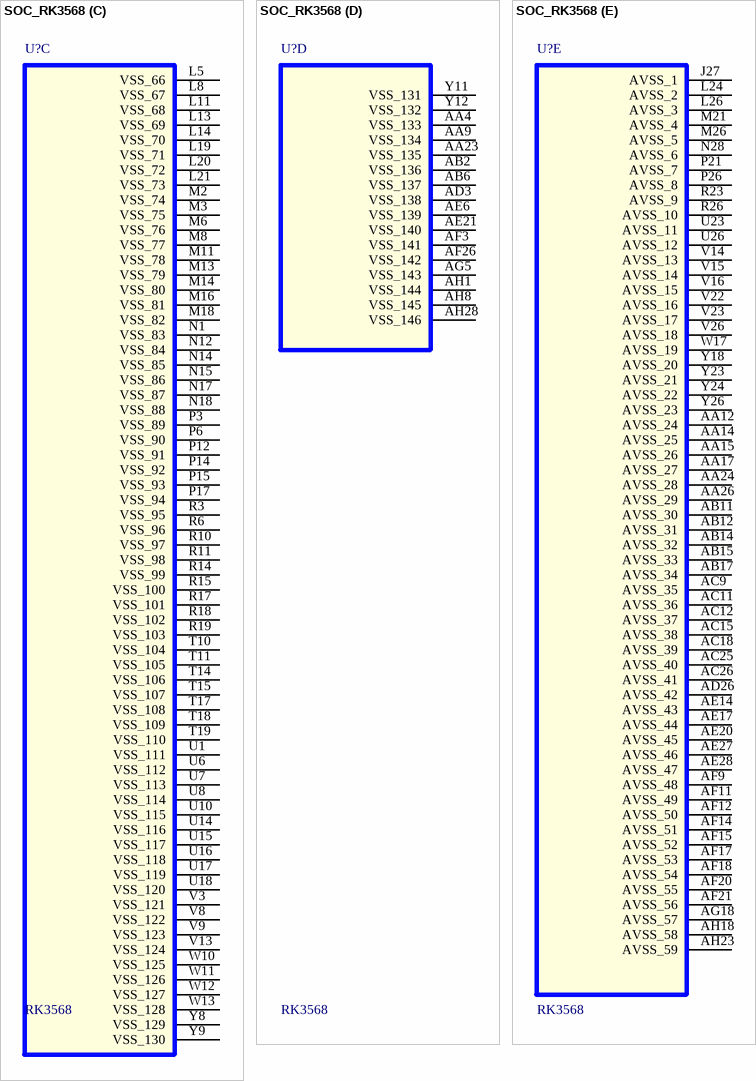
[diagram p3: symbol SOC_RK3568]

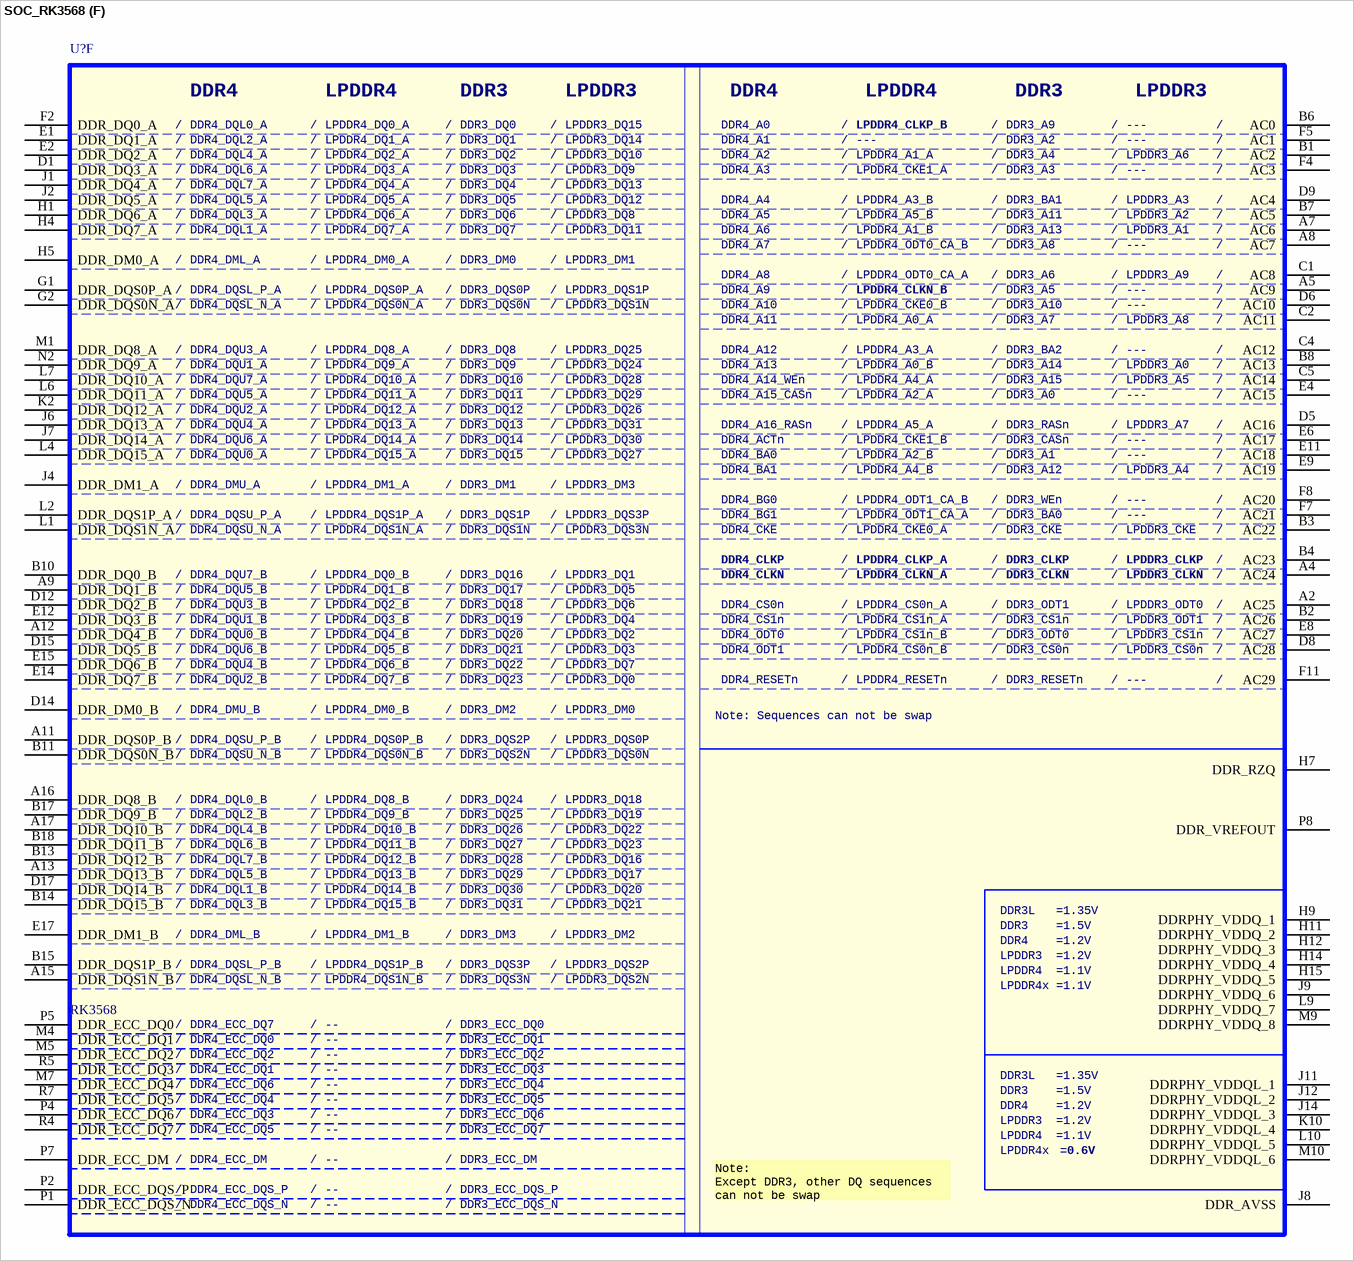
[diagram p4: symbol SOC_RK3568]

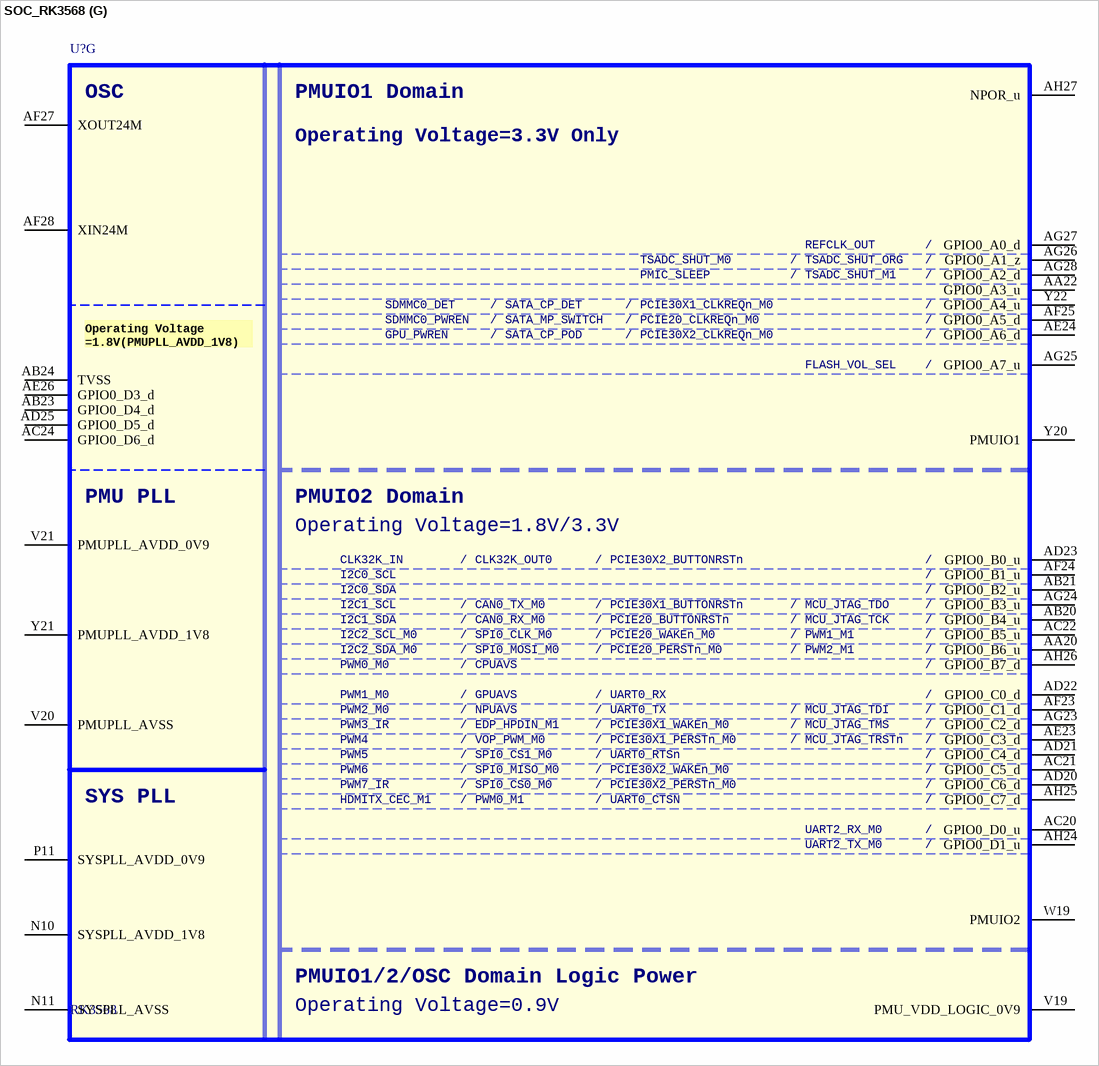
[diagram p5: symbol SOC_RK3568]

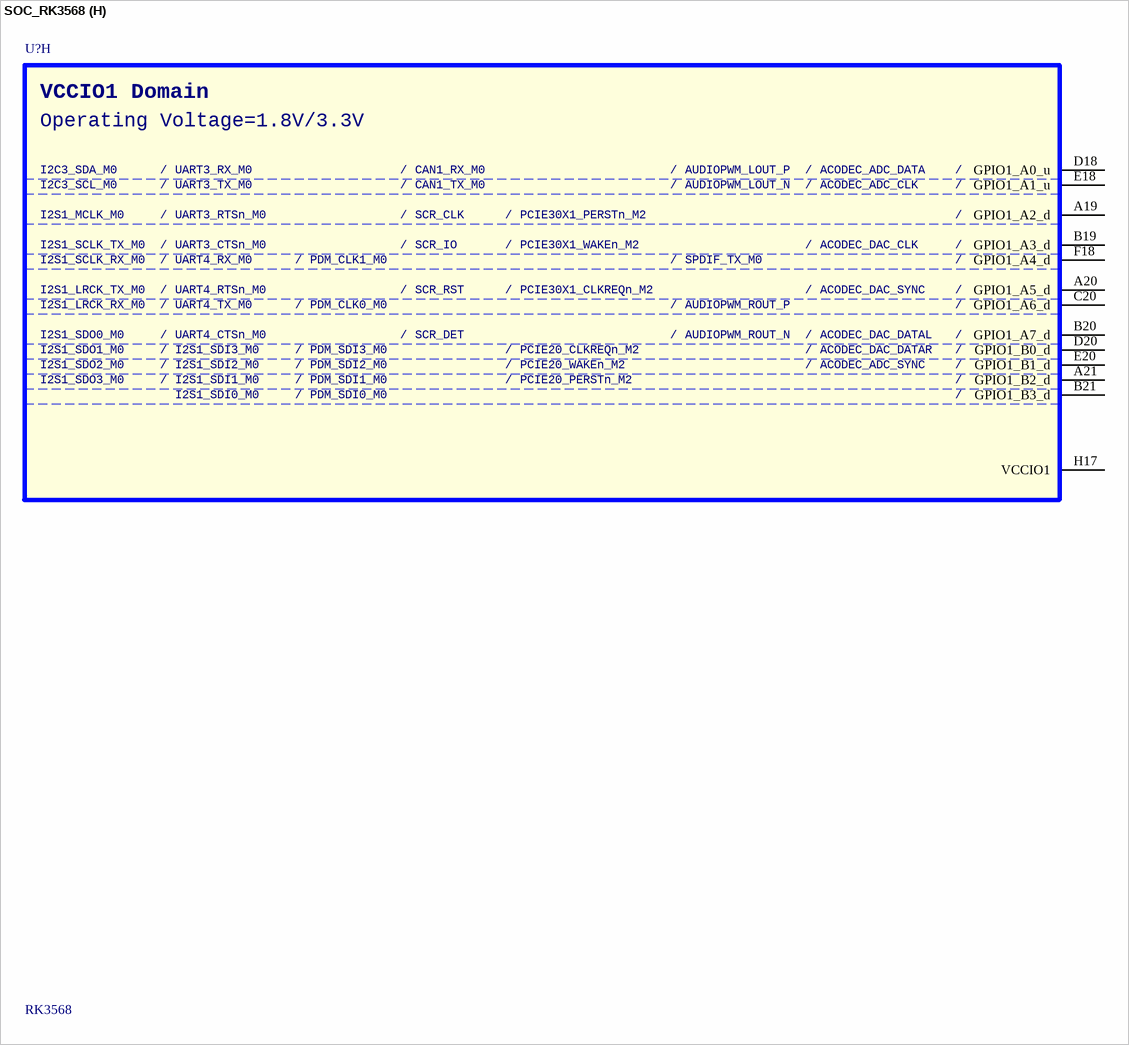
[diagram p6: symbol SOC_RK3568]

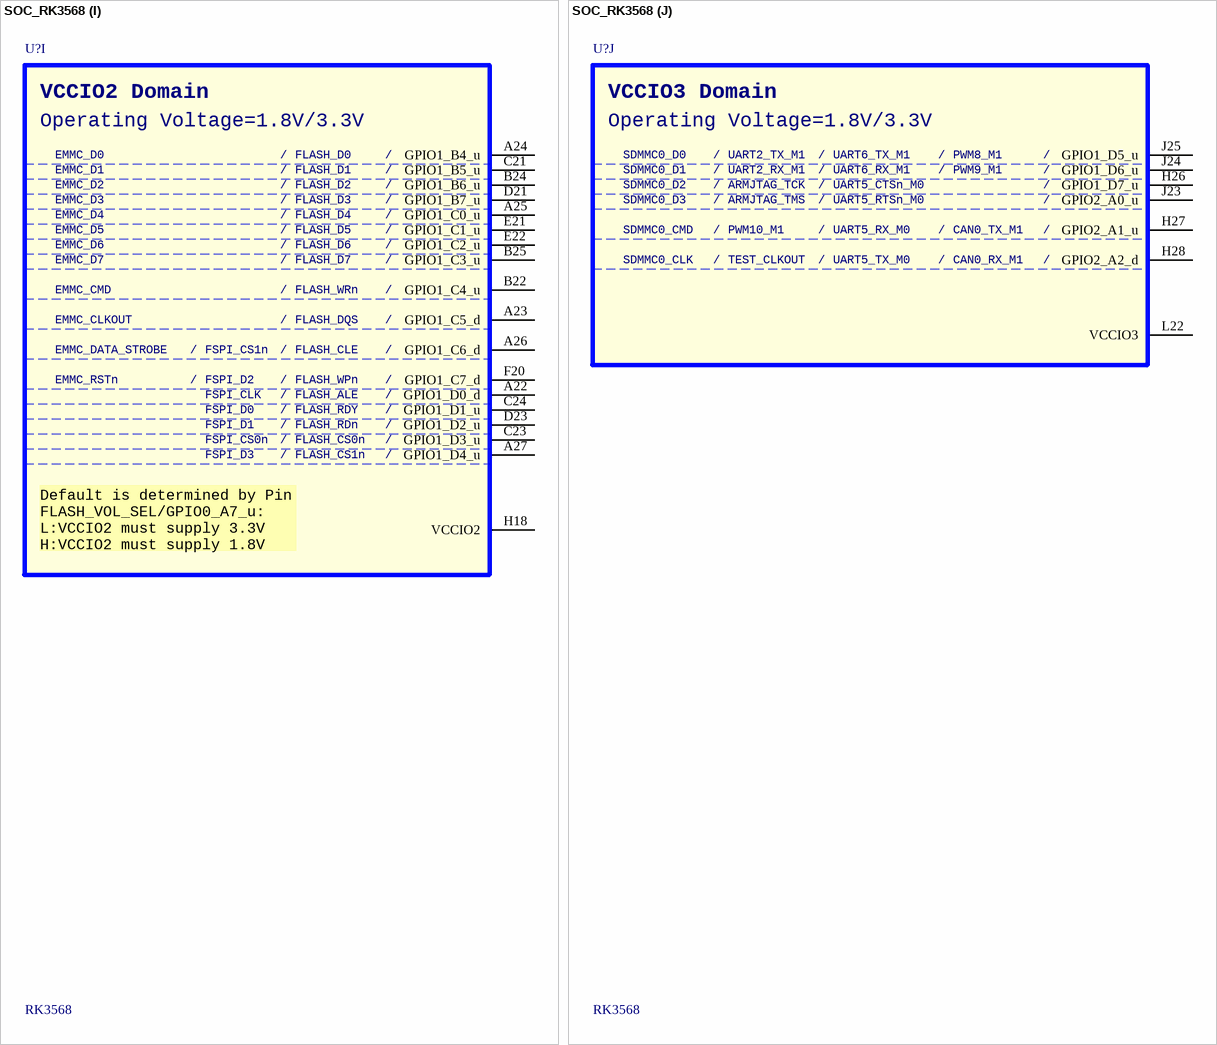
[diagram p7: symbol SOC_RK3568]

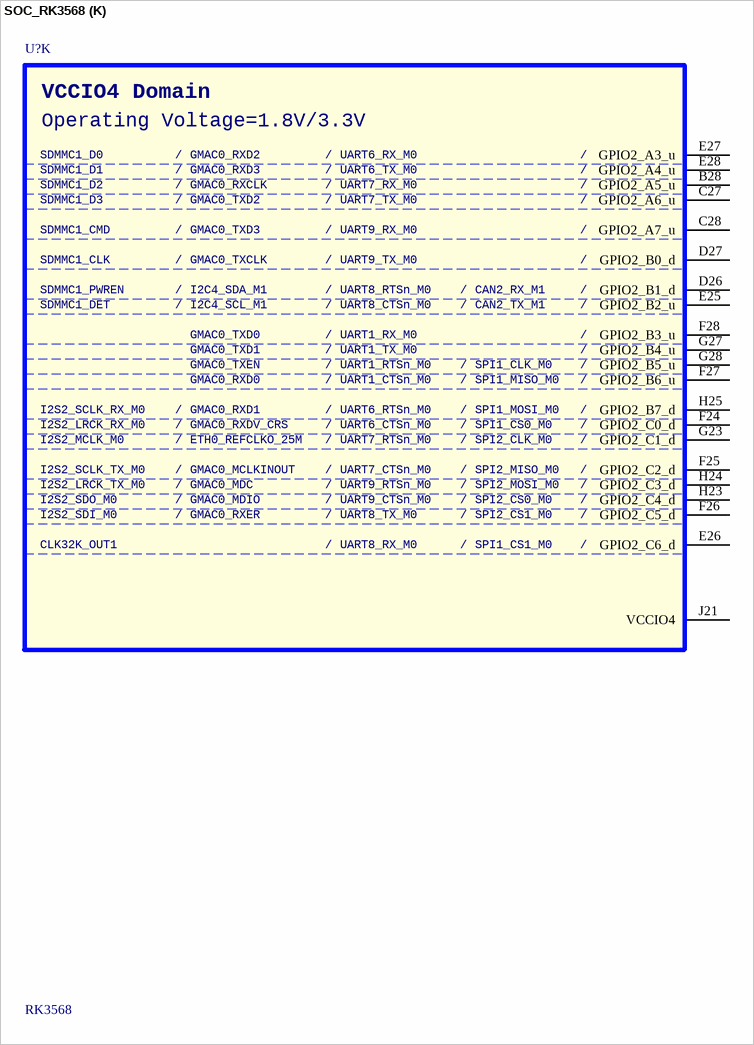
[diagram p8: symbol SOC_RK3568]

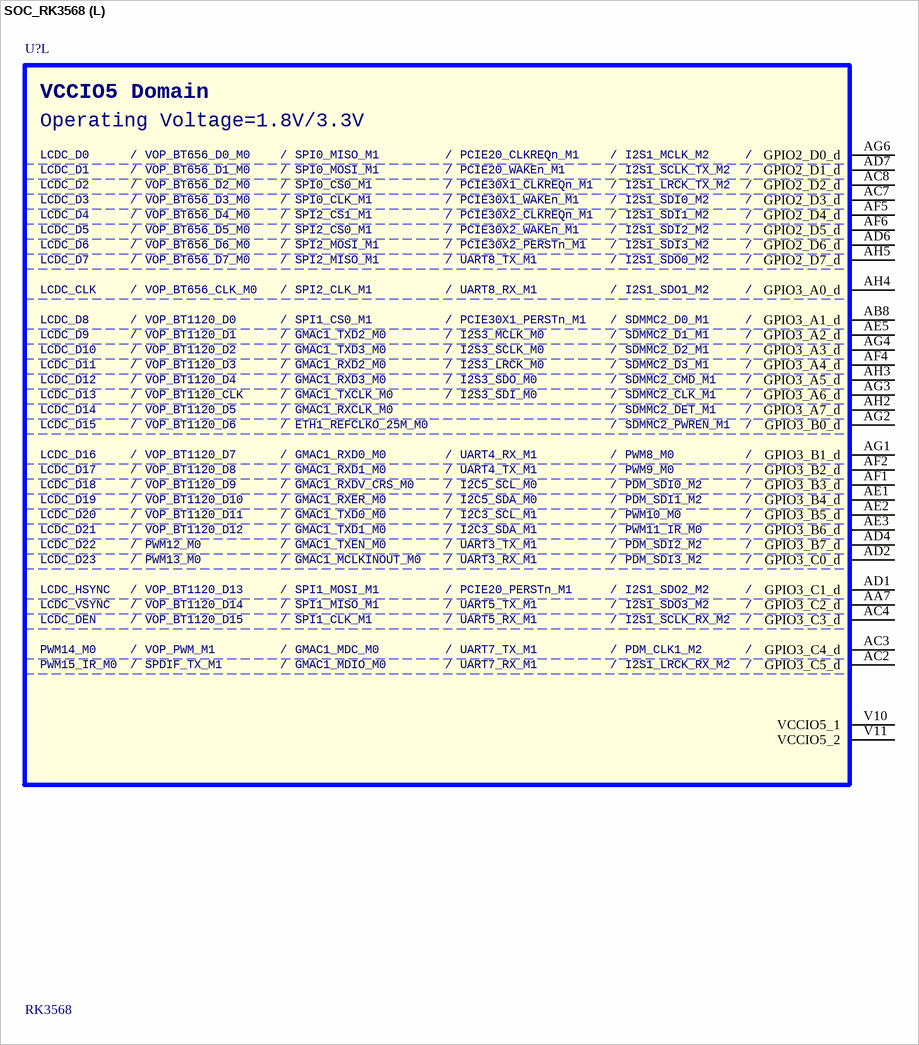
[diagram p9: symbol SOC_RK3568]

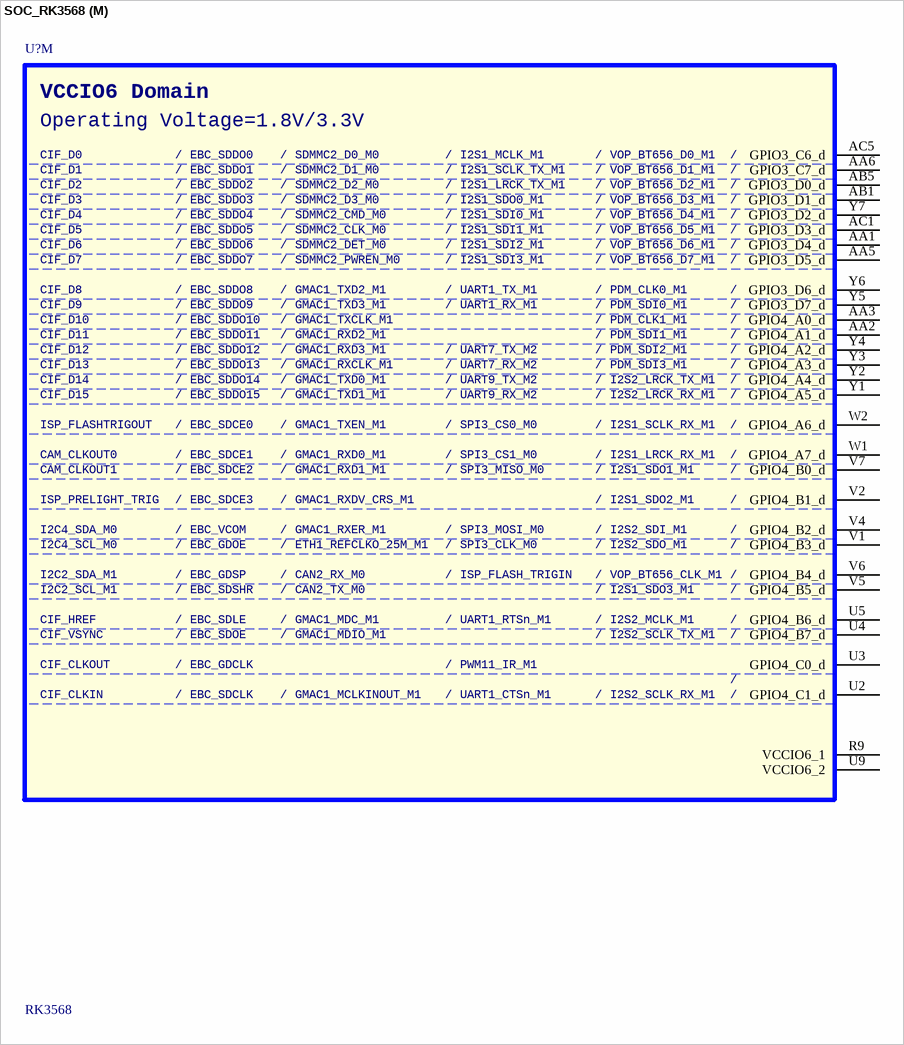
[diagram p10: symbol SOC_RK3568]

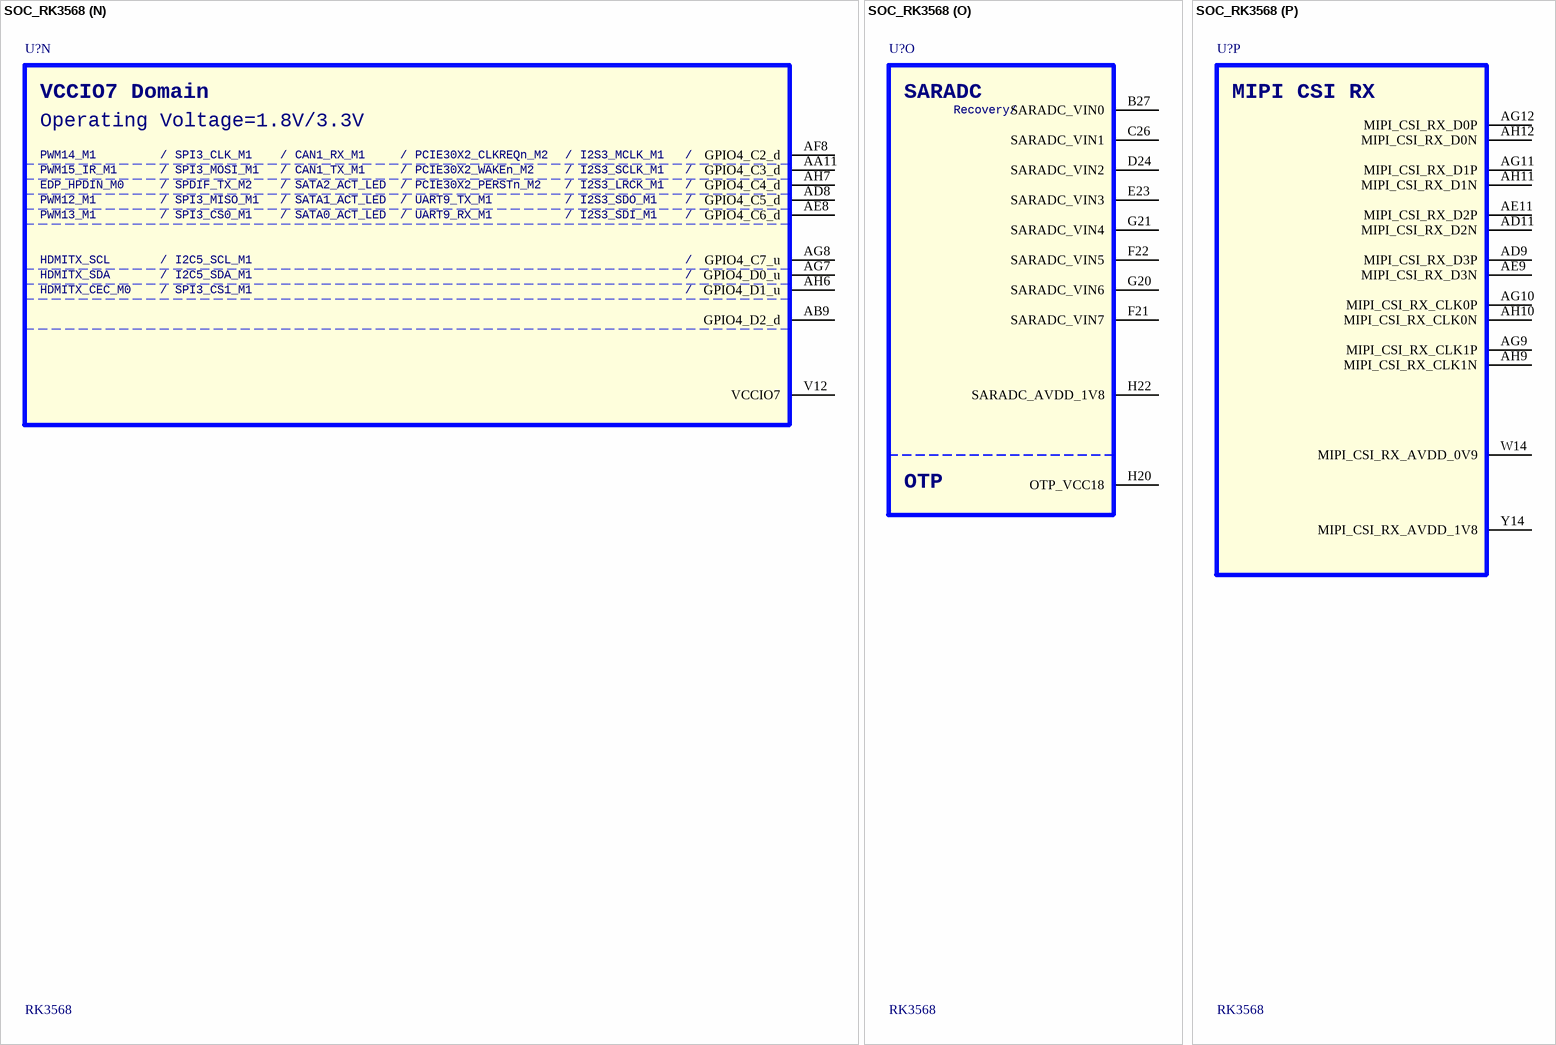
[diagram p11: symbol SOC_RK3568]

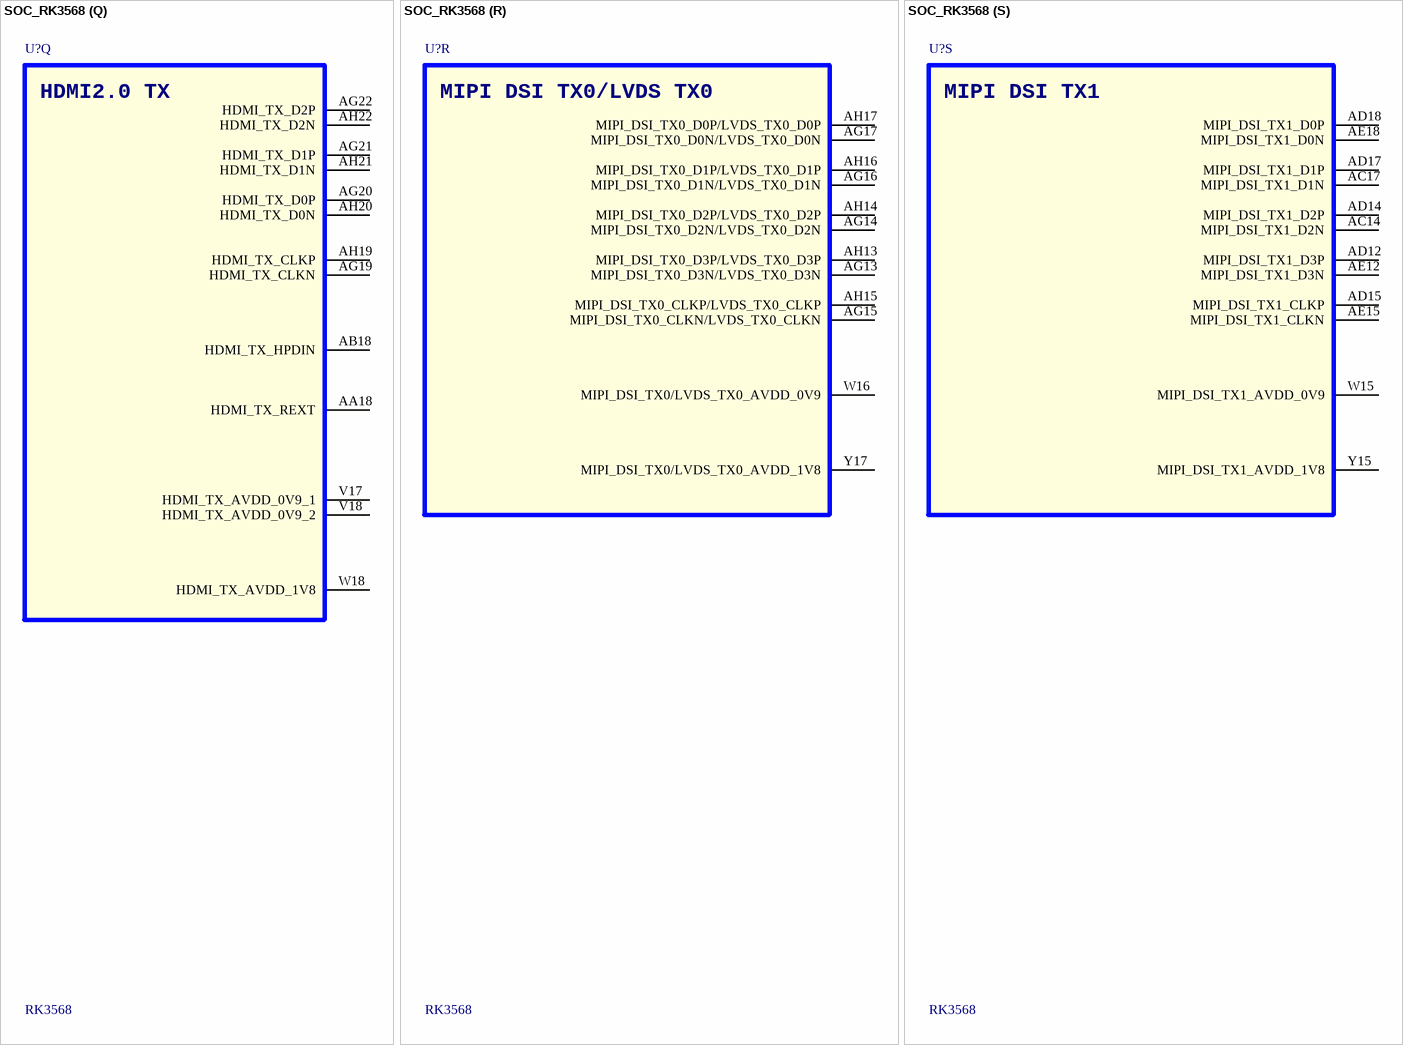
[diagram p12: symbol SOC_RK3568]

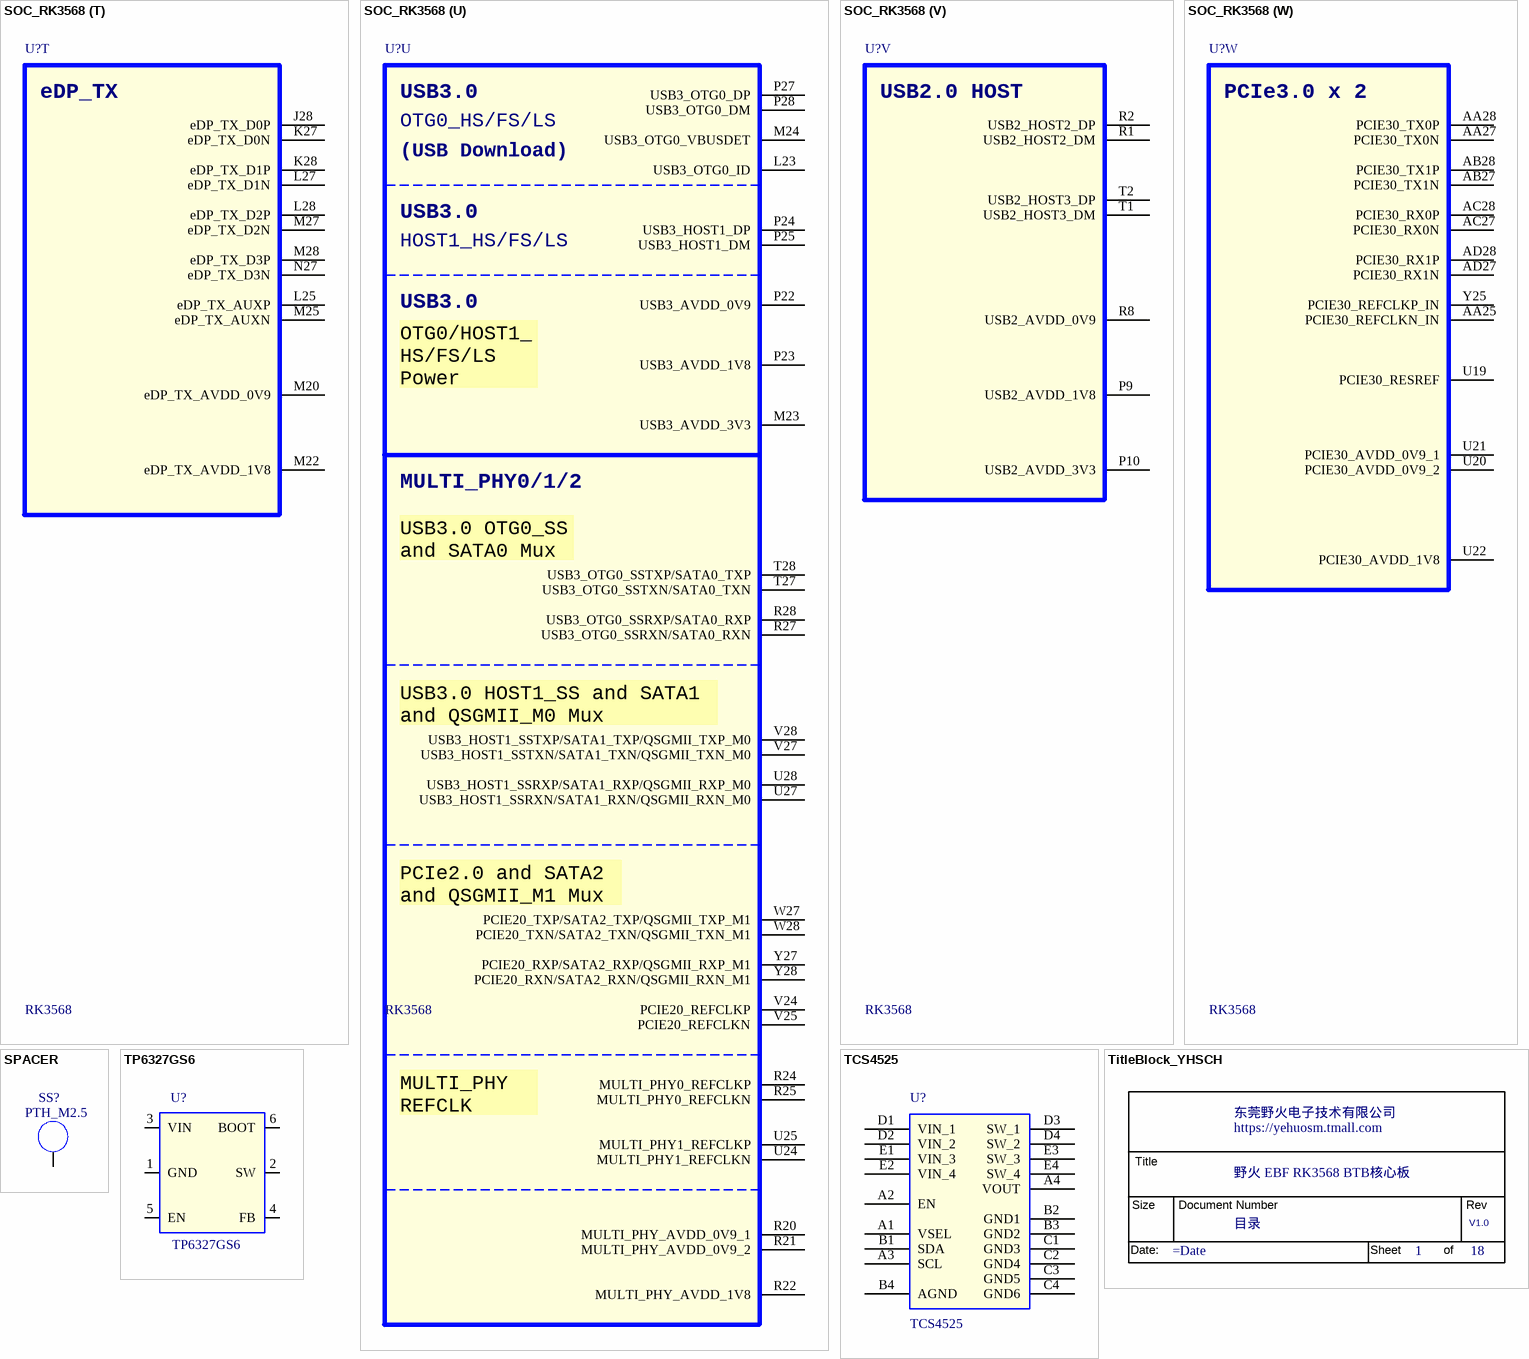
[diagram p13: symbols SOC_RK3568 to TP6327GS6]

## SOC_RK3568
designator U?, comment RK3568
SWAP_INFO: (S1+S2+S3+S4+S5+S6+S7+S8+S9+S10+S11+S12+S13+S14+S15+S16+S17+S18+S19+S20+S21+S22+S23); SPLIT_INST: TRUE; 规格: 四核64位Cortex-A55 主频最高2.0GHz 接口USB2.0/USB3.0/PCIE3.0/PCIE2.1/SATA3.0/QSGMII; 条码: EBF29130005; 品牌: 瑞芯微; 类别: 应用处理器; 规格书: Rockchip RK3568 Datasheet V1.2-20210601.pdf; 生命周期: 量产
footprint BGA636_1
footprint bga636_19r00x19r00x1r20
part A pins: J15 VDD_CPU_1, K15 VDD_CPU_2, K16 VDD_CPU_3, K17 VDD_CPU_4, K18 VDD_CPU_5, L12 VDD_LOGIC_1, L15 VDD_CPU_6, L16 VDD_CPU_7, L17 VDD_CPU_8, L18 VDD_CPU_9, M12 VDD_LOGIC_2, M15 VDD_CPU_COM, M17 VDD_CPU_10, M19 VDD_NPU_1, N13 VDD_LOGIC_3, N16 VDD_LOGIC_4, N19 VDD_NPU_2, P13 VDD_LOGIC_5, P16 VDD_LOGIC_6, P18 VDD_NPU_3, P19 VDD_NPU_4, P20 VDD_NPU_5, R12 VDD_LOGIC_7, R13 VDD_GPU_1, R16 VDD_LOGIC_8, T12 VDD_LOGIC_9, T13 VDD_GPU_2, T16 VDD_LOGIC_10, U11 VDD_GPU_3, U12 VDD_GPU_4, U13 VDD_GPU_5
part B pins: A1 VSS_1, A3 VSS_2, A6 VSS_3, A10 VSS_4, A14 VSS_5, A18 VSS_6, A28 VSS_7, B5 VSS_8, B9 VSS_9, B12 VSS_10, B16 VSS_11, B23 VSS_12, B26 VSS_13, C3 VSS_14, C6 VSS_15, C8 VSS_16, C9 VSS_17, C11 VSS_18, C12 VSS_19, C14 VSS_20, C15 VSS_21, C17 VSS_22, C18 VSS_23, C25 VSS_24, D2 VSS_25, D3 VSS_26, D11 VSS_27, D28 VSS_28, E3 VSS_29, E7 VSS_30, F1 VSS_31, F3 VSS_32, F9 VSS_33, F12 VSS_34, F14 VSS_35, F15 VSS_36, F17 VSS_37, G5 VSS_38, G6 VSS_39, G8 VSS_40, G9 VSS_41, G11 VSS_42, G12 VSS_43, G14 VSS_44, G15 VSS_45, G17 VSS_46, G18 VSS_47, G24 VSS_48, H2 VSS_49, H3 VSS_50, H6 VSS_51, J3 VSS_52, J5 VSS_53, J17 VSS_54, J18 VSS_55, J20 VSS_56, J22 VSS_57, J26 VSS_58, K1 VSS_59, K11 VSS_60, K12 VSS_61, K13 VSS_62, K14 VSS_63, K19 VSS_64, L3 VSS_65
part C pins: L5 VSS_66, L8 VSS_67, L11 VSS_68, L13 VSS_69, L14 VSS_70, L19 VSS_71, L20 VSS_72, L21 VSS_73, M2 VSS_74, M3 VSS_75, M6 VSS_76, M8 VSS_77, M11 VSS_78, M13 VSS_79, M14 VSS_80, M16 VSS_81, M18 VSS_82, N1 VSS_83, N12 VSS_84, N14 VSS_85, N15 VSS_86, N17 VSS_87, N18 VSS_88, P3 VSS_89, P6 VSS_90, P12 VSS_91, P14 VSS_92, P15 VSS_93, P17 VSS_94, R3 VSS_95, R6 VSS_96, R10 VSS_97, R11 VSS_98, R14 VSS_99, R15 VSS_100, R17 VSS_101, R18 VSS_102, R19 VSS_103, T10 VSS_104, T11 VSS_105, T14 VSS_106, T15 VSS_107, T17 VSS_108, T18 VSS_109, T19 VSS_110, U1 VSS_111, U6 VSS_112, U7 VSS_113, U8 VSS_114, U10 VSS_115, U14 VSS_116, U15 VSS_117, U16 VSS_118, U17 VSS_119, U18 VSS_120, V3 VSS_121, V8 VSS_122, V9 VSS_123, V13 VSS_124, W10 VSS_125, W11 VSS_126, W12 VSS_127, W13 VSS_128, Y8 VSS_129, Y9 VSS_130
part D pins: AA4 VSS_133, AA9 VSS_134, AA23 VSS_135, AB2 VSS_136, AB6 VSS_137, AD3 VSS_138, AE6 VSS_139, AE21 VSS_140, AF3 VSS_141, AF26 VSS_142, AG5 VSS_143, AH1 VSS_144, AH8 VSS_145, AH28 VSS_146, Y11 VSS_131, Y12 VSS_132
part E pins: AA12 AVSS_24, AA14 AVSS_25, AA15 AVSS_26, AA17 AVSS_27, AA24 AVSS_28, AA26 AVSS_29, AB11 AVSS_30, AB12 AVSS_31, AB14 AVSS_32, AB15 AVSS_33, AB17 AVSS_34, AC9 AVSS_35, AC11 AVSS_36, AC12 AVSS_37, AC15 AVSS_38, AC18 AVSS_39, AC25 AVSS_40, AC26 AVSS_41, AD26 AVSS_42, AE14 AVSS_43, AE17 AVSS_44, AE20 AVSS_45, AE27 AVSS_46, AE28 AVSS_47, AF9 AVSS_48, AF11 AVSS_49, AF12 AVSS_50, AF14 AVSS_51, AF15 AVSS_52, AF17 AVSS_53, AF18 AVSS_54, AF20 AVSS_55, AF21 AVSS_56, AG18 AVSS_57, AH18 AVSS_58, AH23 AVSS_59, J27 AVSS_1, L24 AVSS_2, L26 AVSS_3, M21 AVSS_4, M26 AVSS_5, N28 AVSS_6, P21 AVSS_7, P26 AVSS_8, R23 AVSS_9, R26 AVSS_10, U23 AVSS_11, U26 AVSS_12, V14 AVSS_13, V15 AVSS_14, V16 AVSS_15, V22 AVSS_16, V23 AVSS_17, V26 AVSS_18, W17 AVSS_19, Y18 AVSS_20, Y23 AVSS_21, Y24 AVSS_22, Y26 AVSS_23
part F pins: A2 AC25, A4 AC24, A5 AC9, A7 AC6, A8 AC7, A9 DDR_DQ1_B, A11 DDR_DQS0P_B, A12 DDR_DQ4_B, A13 DDR_DQ13_B, A15 DDR_DQS1N_B, A16 DDR_DQ8_B, A17 DDR_DQ10_B, B1 AC2, B2 AC26, B3 AC22, B4 AC23, B6 AC0, B7 AC5, B8 AC13, B10 DDR_DQ0_B, B11 DDR_DQS0N_B, B13 DDR_DQ12_B, B14 DDR_DQ15_B, B15 DDR_DQS1P_B, B17 DDR_DQ9_B, B18 DDR_DQ11_B, C1 AC8, C2 AC11, C4 AC12, C5 AC14, D1 DDR_DQ3_A, D5 AC16, D6 AC10, D8 AC28, D9 AC4, D12 DDR_DQ2_B, D14 DDR_DM0_B, D15 DDR_DQ5_B, D17 DDR_DQ14_B, E1 DDR_DQ1_A, E2 DDR_DQ2_A, E4 AC15, E6 AC17, E8 AC27, E9 AC19, E11 AC18, E12 DDR_DQ3_B, E14 DDR_DQ7_B, E15 DDR_DQ6_B, E17 DDR_DM1_B, F2 DDR_DQ0_A, F4 AC3, F5 AC1, F7 AC21, F8 AC20, F11 AC29, G1 DDR_DQS0P_A, G2 DDR_DQS0N_A, H1 DDR_DQ6_A, H4 DDR_DQ7_A, H5 DDR_DM0_A, H7 DDR_RZQ, H9 DDRPHY_VDDQ_1, H11 DDRPHY_VDDQ_2, H12 DDRPHY_VDDQ_3, H14 DDRPHY_VDDQ_4, H15 DDRPHY_VDDQ_5, J1 DDR_DQ4_A, J2 DDR_DQ5_A, J4 DDR_DM1_A, J6 DDR_DQ13_A, J7 DDR_DQ14_A, J8 DDR_AVSS, J9 DDRPHY_VDDQ_6, J11 DDRPHY_VDDQL_1, J12 DDRPHY_VDDQL_2, J14 DDRPHY_VDDQL_3, K2 DDR_DQ12_A, K10 DDRPHY_VDDQL_4, L1 DDR_DQS1N_A, L2 DDR_DQS1P_A, L4 DDR_DQ15_A, L6 DDR_DQ11_A, L7 DDR_DQ10_A, L9 DDRPHY_VDDQ_7, L10 DDRPHY_VDDQL_5, M1 DDR_DQ8_A, M4 DDR_ECC_DQ1, M5 DDR_ECC_DQ2, M7 DDR_ECC_DQ4, M9 DDRPHY_VDDQ_8, M10 DDRPHY_VDDQL_6, N2 DDR_DQ9_A, P1 DDR_ECC_DQS_N, P2 DDR_ECC_DQS_P, P4 DDR_ECC_DQ6, P5 DDR_ECC_DQ0, P7 DDR_ECC_DM, P8 DDR_VREFOUT, R4 DDR_ECC_DQ7, R5 DDR_ECC_DQ3, R7 DDR_ECC_DQ5
part G pins: AA20 GPIO0_B6_u, AA22 GPIO0_A3_u, AB20 GPIO0_B4_u, AB21 GPIO0_B2_u, AB23 GPIO0_D4_d, AB24 TVSS, AC20 GPIO0_D0_u, AC21 GPIO0_C5_d, AC22 GPIO0_B5_u, AC24 GPIO0_D6_d, AD20 GPIO0_C6_d, AD21 GPIO0_C4_d, AD22 GPIO0_C0_d, AD23 GPIO0_B0_u, AD25 GPIO0_D5_d, AE23 GPIO0_C3_d, AE24 GPIO0_A6_d, AE26 GPIO0_D3_d, AF23 GPIO0_C1_d, AF24 GPIO0_B1_u, AF25 GPIO0_A5_d, AF27 XOUT24M, AF28 XIN24M, AG23 GPIO0_C2_d, AG24 GPIO0_B3_u, AG25 GPIO0_A7_u, AG26 GPIO0_A1_z, AG27 GPIO0_A0_d, AG28 GPIO0_A2_d, AH24 GPIO0_D1_u, AH25 GPIO0_C7_d, AH26 GPIO0_B7_d, AH27 NPOR_u, N10 SYSPLL_AVDD_1V8, N11 SYSPLL_AVSS, P11 SYSPLL_AVDD_0V9, V19 PMU_VDD_LOGIC_0V9, V20 PMUPLL_AVSS, V21 PMUPLL_AVDD_0V9, W19 PMUIO2, Y20 PMUIO1, Y21 PMUPLL_AVDD_1V8, Y22 GPIO0_A4_u
part H pins: A19 GPIO1_A2_d, A20 GPIO1_A5_d, A21 GPIO1_B2_d, B19 GPIO1_A3_d, B20 GPIO1_A7_d, B21 GPIO1_B3_d, C20 GPIO1_A6_d, D18 GPIO1_A0_u, D20 GPIO1_B0_d, E18 GPIO1_A1_u, E20 GPIO1_B1_d, F18 GPIO1_A4_d, H17 VCCIO1
part I pins: A22 GPIO1_D0_d, A23 GPIO1_C5_d, A24 GPIO1_B4_u, A25 GPIO1_C0_u, A26 GPIO1_C6_d, A27 GPIO1_D4_u, B22 GPIO1_C4_u, B24 GPIO1_B6_u, B25 GPIO1_C3_u, C21 GPIO1_B5_u, C23 GPIO1_D3_u, C24 GPIO1_D1_u, D21 GPIO1_B7_u, D23 GPIO1_D2_u, E21 GPIO1_C1_u, E22 GPIO1_C2_u, F20 GPIO1_C7_d, H18 VCCIO2
part J pins: H26 GPIO1_D7_u, H27 GPIO2_A1_u, H28 GPIO2_A2_d, J23 GPIO2_A0_u, J24 GPIO1_D6_u, J25 GPIO1_D5_u, L22 VCCIO3
part K pins: B28 GPIO2_A5_u, C27 GPIO2_A6_u, C28 GPIO2_A7_u, D26 GPIO2_B1_d, D27 GPIO2_B0_d, E25 GPIO2_B2_u, E26 GPIO2_C6_d, E27 GPIO2_A3_u, E28 GPIO2_A4_u, F24 GPIO2_C0_d, F25 GPIO2_C2_d, F26 GPIO2_C5_d, F27 GPIO2_B6_u, F28 GPIO2_B3_u, G23 GPIO2_C1_d, G27 GPIO2_B4_u, G28 GPIO2_B5_u, H23 GPIO2_C4_d, H24 GPIO2_C3_d, H25 GPIO2_B7_d, J21 VCCIO4
part L pins: AA7 GPIO3_C2_d, AB8 GPIO3_A1_d, AC2 GPIO3_C5_d, AC3 GPIO3_C4_d, AC4 GPIO3_C3_d, AC7 GPIO2_D3_d, AC8 GPIO2_D2_d, AD1 GPIO3_C1_d, AD2 GPIO3_C0_d, AD4 GPIO3_B7_d, AD6 GPIO2_D6_d, AD7 GPIO2_D1_d, AE1 GPIO3_B4_d, AE2 GPIO3_B5_d, AE3 GPIO3_B6_d, AE5 GPIO3_A2_d, AF1 GPIO3_B3_d, AF2 GPIO3_B2_d, AF4 GPIO3_A4_d, AF5 GPIO2_D4_d, AF6 GPIO2_D5_d, AG1 GPIO3_B1_d, AG2 GPIO3_B0_d, AG3 GPIO3_A6_d, AG4 GPIO3_A3_d, AG6 GPIO2_D0_d, AH2 GPIO3_A7_d, AH3 GPIO3_A5_d, AH4 GPIO3_A0_d, AH5 GPIO2_D7_d, V10 VCCIO5_1, V11 VCCIO5_2
part M pins: AA1 GPIO3_D4_d, AA2 GPIO4_A1_d, AA3 GPIO4_A0_d, AA5 GPIO3_D5_d, AA6 GPIO3_C7_d, AB1 GPIO3_D1_d, AB5 GPIO3_D0_d, AC1 GPIO3_D3_d, AC5 GPIO3_C6_d, R9 VCCIO6_1, U2 GPIO4_C1_d, U3 GPIO4_C0_d, U4 GPIO4_B7_d, U5 GPIO4_B6_d, U9 VCCIO6_2, V1 GPIO4_B3_d, V2 GPIO4_B1_d, V4 GPIO4_B2_d, V5 GPIO4_B5_d, V6 GPIO4_B4_d, V7 GPIO4_B0_d, W1 GPIO4_A7_d, W2 GPIO4_A6_d, Y1 GPIO4_A5_d, Y2 GPIO4_A4_d, Y3 GPIO4_A3_d, Y4 GPIO4_A2_d, Y5 GPIO3_D7_d, Y6 GPIO3_D6_d, Y7 GPIO3_D2_d
part N pins: AA11 GPIO4_C3_d, AB9 GPIO4_D2_d, AD8 GPIO4_C5_d, AE8 GPIO4_C6_d, AF8 GPIO4_C2_d, AG7 GPIO4_D0_u, AG8 GPIO4_C7_u, AH6 GPIO4_D1_u, AH7 GPIO4_C4_d, V12 VCCIO7
part O pins: B27 SARADC_VIN0, C26 SARADC_VIN1, D24 SARADC_VIN2, E23 SARADC_VIN3, F21 SARADC_VIN7, F22 SARADC_VIN5, G20 SARADC_VIN6, G21 SARADC_VIN4, H20 OTP_VCC18, H22 SARADC_AVDD_1V8
part P pins: AD9 MIPI_CSI_RX_D3P, AD11 MIPI_CSI_RX_D2N, AE9 MIPI_CSI_RX_D3N, AE11 MIPI_CSI_RX_D2P, AG9 MIPI_CSI_RX_CLK1P, AG10 MIPI_CSI_RX_CLK0P, AG11 MIPI_CSI_RX_D1P, AG12 MIPI_CSI_RX_D0P, AH9 MIPI_CSI_RX_CLK1N, AH10 MIPI_CSI_RX_CLK0N, AH11 MIPI_CSI_RX_D1N, AH12 MIPI_CSI_RX_D0N, W14 MIPI_CSI_RX_AVDD_0V9, Y14 MIPI_CSI_RX_AVDD_1V8
part Q pins: AA18 HDMI_TX_REXT, AB18 HDMI_TX_HPDIN, AG19 HDMI_TX_CLKN, AG20 HDMI_TX_D0P, AG21 HDMI_TX_D1P, AG22 HDMI_TX_D2P, AH19 HDMI_TX_CLKP, AH20 HDMI_TX_D0N, AH21 HDMI_TX_D1N, AH22 HDMI_TX_D2N, V17 HDMI_TX_AVDD_0V9_1, V18 HDMI_TX_AVDD_0V9_2, W18 HDMI_TX_AVDD_1V8
part R pins: AG13 MIPI_DSI_TX0_D3N/LVDS_TX0_D3N, AG14 MIPI_DSI_TX0_D2N/LVDS_TX0_D2N, AG15 MIPI_DSI_TX0_CLKN/LVDS_TX0_CLKN, AG16 MIPI_DSI_TX0_D1N/LVDS_TX0_D1N, AG17 MIPI_DSI_TX0_D0N/LVDS_TX0_D0N, AH13 MIPI_DSI_TX0_D3P/LVDS_TX0_D3P, AH14 MIPI_DSI_TX0_D2P/LVDS_TX0_D2P, AH15 MIPI_DSI_TX0_CLKP/LVDS_TX0_CLKP, AH16 MIPI_DSI_TX0_D1P/LVDS_TX0_D1P, AH17 MIPI_DSI_TX0_D0P/LVDS_TX0_D0P, W16 MIPI_DSI_TX0/LVDS_TX0_AVDD_0V9, Y17 MIPI_DSI_TX0/LVDS_TX0_AVDD_1V8
part S pins: AC14 MIPI_DSI_TX1_D2N, AC17 MIPI_DSI_TX1_D1N, AD12 MIPI_DSI_TX1_D3P, AD14 MIPI_DSI_TX1_D2P, AD15 MIPI_DSI_TX1_CLKP, AD17 MIPI_DSI_TX1_D1P, AD18 MIPI_DSI_TX1_D0P, AE12 MIPI_DSI_TX1_D3N, AE15 MIPI_DSI_TX1_CLKN, AE18 MIPI_DSI_TX1_D0N, W15 MIPI_DSI_TX1_AVDD_0V9, Y15 MIPI_DSI_TX1_AVDD_1V8
part T pins: J28 eDP_TX_D0P, K27 eDP_TX_D0N, K28 eDP_TX_D1P, L25 eDP_TX_AUXP, L27 eDP_TX_D1N, L28 eDP_TX_D2P, M20 eDP_TX_AVDD_0V9, M22 eDP_TX_AVDD_1V8, M25 eDP_TX_AUXN, M27 eDP_TX_D2N, M28 eDP_TX_D3P, N27 eDP_TX_D3N
part U pins: L23 USB3_OTG0_ID, M23 USB3_AVDD_3V3, M24 USB3_OTG0_VBUSDET, P22 USB3_AVDD_0V9, P23 USB3_AVDD_1V8, P24 USB3_HOST1_DP, P25 USB3_HOST1_DM, P27 USB3_OTG0_DP, P28 USB3_OTG0_DM, R20 MULTI_PHY_AVDD_0V9_1, R21 MULTI_PHY_AVDD_0V9_2, R22 MULTI_PHY_AVDD_1V8, R24 MULTI_PHY0_REFCLKP, R25 MULTI_PHY0_REFCLKN, R27 USB3_OTG0_SSRXN/SATA0_RXN, R28 USB3_OTG0_SSRXP/SATA0_RXP, T27 USB3_OTG0_SSTXN/SATA0_TXN, T28 USB3_OTG0_SSTXP/SATA0_TXP, U24 MULTI_PHY1_REFCLKN, U25 MULTI_PHY1_REFCLKP, U27 USB3_HOST1_SSRXN/SATA1_RXN/QSGMII_RXN_M0, U28 USB3_HOST1_SSRXP/SATA1_RXP/QSGMII_RXP_M0, V24 PCIE20_REFCLKP, V25 PCIE20_REFCLKN, V27 USB3_HOST1_SSTXN/SATA1_TXN/QSGMII_TXN_M0, V28 USB3_HOST1_SSTXP/SATA1_TXP/QSGMII_TXP_M0, W27 PCIE20_TXP/SATA2_TXP/QSGMII_TXP_M1, W28 PCIE20_TXN/SATA2_TXN/QSGMII_TXN_M1, Y27 PCIE20_RXP/SATA2_RXP/QSGMII_RXP_M1, Y28 PCIE20_RXN/SATA2_RXN/QSGMII_RXN_M1
part V pins: P9 USB2_AVDD_1V8, P10 USB2_AVDD_3V3, R1 USB2_HOST2_DM, R2 USB2_HOST2_DP, R8 USB2_AVDD_0V9, T1 USB2_HOST3_DM, T2 USB2_HOST3_DP
part W pins: AA25 PCIE30_REFCLKN_IN, AA27 PCIE30_TX0N, AA28 PCIE30_TX0P, AB27 PCIE30_TX1N, AB28 PCIE30_TX1P, AC27 PCIE30_RX0N, AC28 PCIE30_RX0P, AD27 PCIE30_RX1N, AD28 PCIE30_RX1P, U19 PCIE30_RESREF, U20 PCIE30_AVDD_0V9_2, U21 PCIE30_AVDD_0V9_1, U22 PCIE30_AVDD_1V8, Y25 PCIE30_REFCLKP_IN

## SPACER
designator SS?, comment PTH_M2.5
CLASS: IC; 生命周期: 量产; 类别: M2.5螺丝孔; 品牌: 野火科技有限公司; 条码: EBFCIS220926100556; 规格编号: M2.5螺丝孔_有铜; PCB Footprint: PTH_M2r5
footprint PTH_M2r5
pins: 1 NC_1

## TCS4525
designator U?
PCB Footprint: csp20_1r96x1r56x0r66; 规格书: TCS4525_Ver.1.0.pdf; 类别: 电源管理-DCDC; 品牌: 汤诚; 条码: EBF29110049; 规格: DC-DC电源芯片 可输出电流 5A 输入电压：2.7V~5.5V 最大输出电压：0.6-1.4V
footprint WLCSP-20
footprint csp20_1r96x1r56x0r66
pins: A1 VSEL, A2 EN, A3 SCL, A4 VOUT, B1 SDA, B2 GND1, B3 GND2, B4 AGND, C1 GND3, C2 GND4, C3 GND5, C4 GND6, D1 VIN_1, D2 VIN_2, D3 SW_1, D4 SW_2, E1 VIN_3, E2 VIN_4, E3 SW_3, E4 SW_4

## TitleBlock_YHSCH
designator *?  Page Count: 18  Page Number: 1  OrgName: 东莞野火电子技术有限公司  Title: 野火 EBF RK3568 BTB核心板  RevCode: V1.0  Doc: 目录  (hidden comment: TitleBlock_YHSCH)  (graphical)

## TP6327GS6
designator U?
PCB Footprint: SOT23_6; 规格: DC-DC电源芯片 可输出电流 3A 开关工作频率 600kHz 输出类型 Adjustable 输出电压的路数 1 最小输入电压 3.5V 最大输入电压 18V; 条码: EBF29110045; 品牌: 台舟; 类别: 电源管理-DCDC; 规格书: TP6327GS6.pdf; 价格: 0.962255; 生命周期: 量产
footprint SOT23_6
pins: 1 GND, 2 SW, 3 VIN, 4 FB, 5 EN, 6 BOOT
